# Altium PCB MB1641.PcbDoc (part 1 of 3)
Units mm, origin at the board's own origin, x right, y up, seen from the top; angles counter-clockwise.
Board outline 70 x 64.48 mm, 4 copper layers (Top Layer, GND, VCC, Bottom Layer), stack 1.502 mm thick; 161 components, 126 nets, 622 pads, 1092 vias.
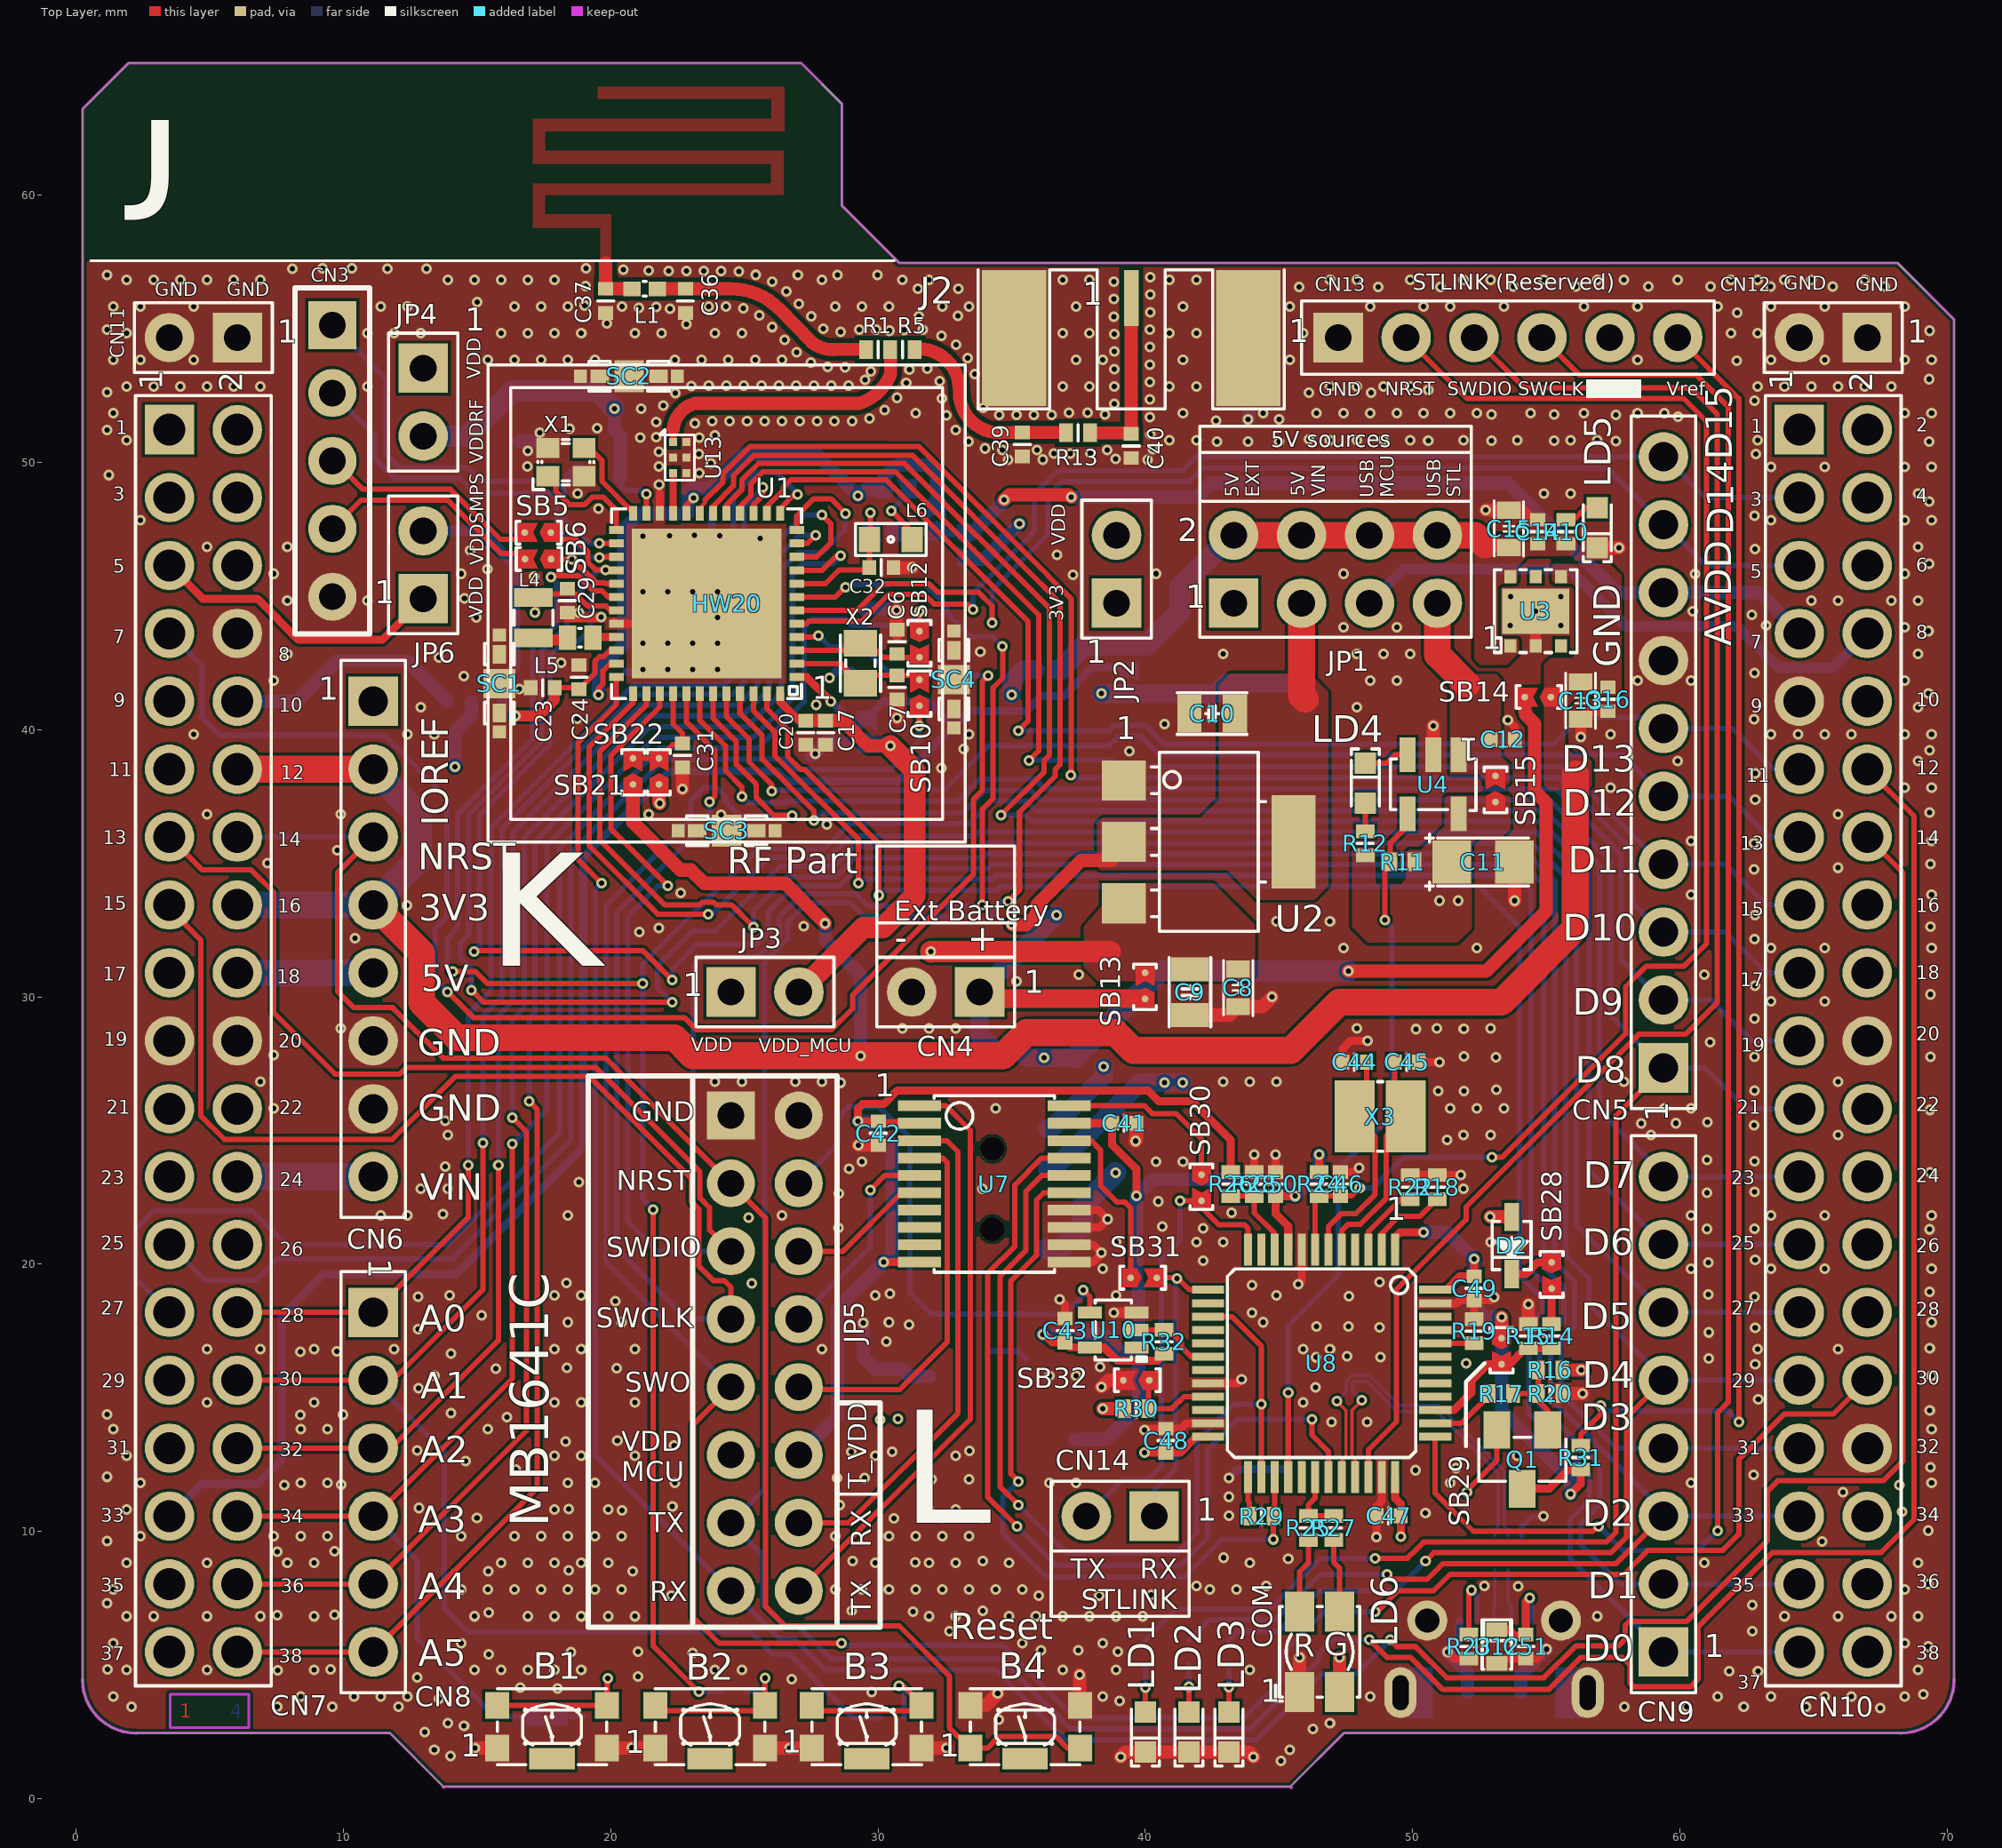
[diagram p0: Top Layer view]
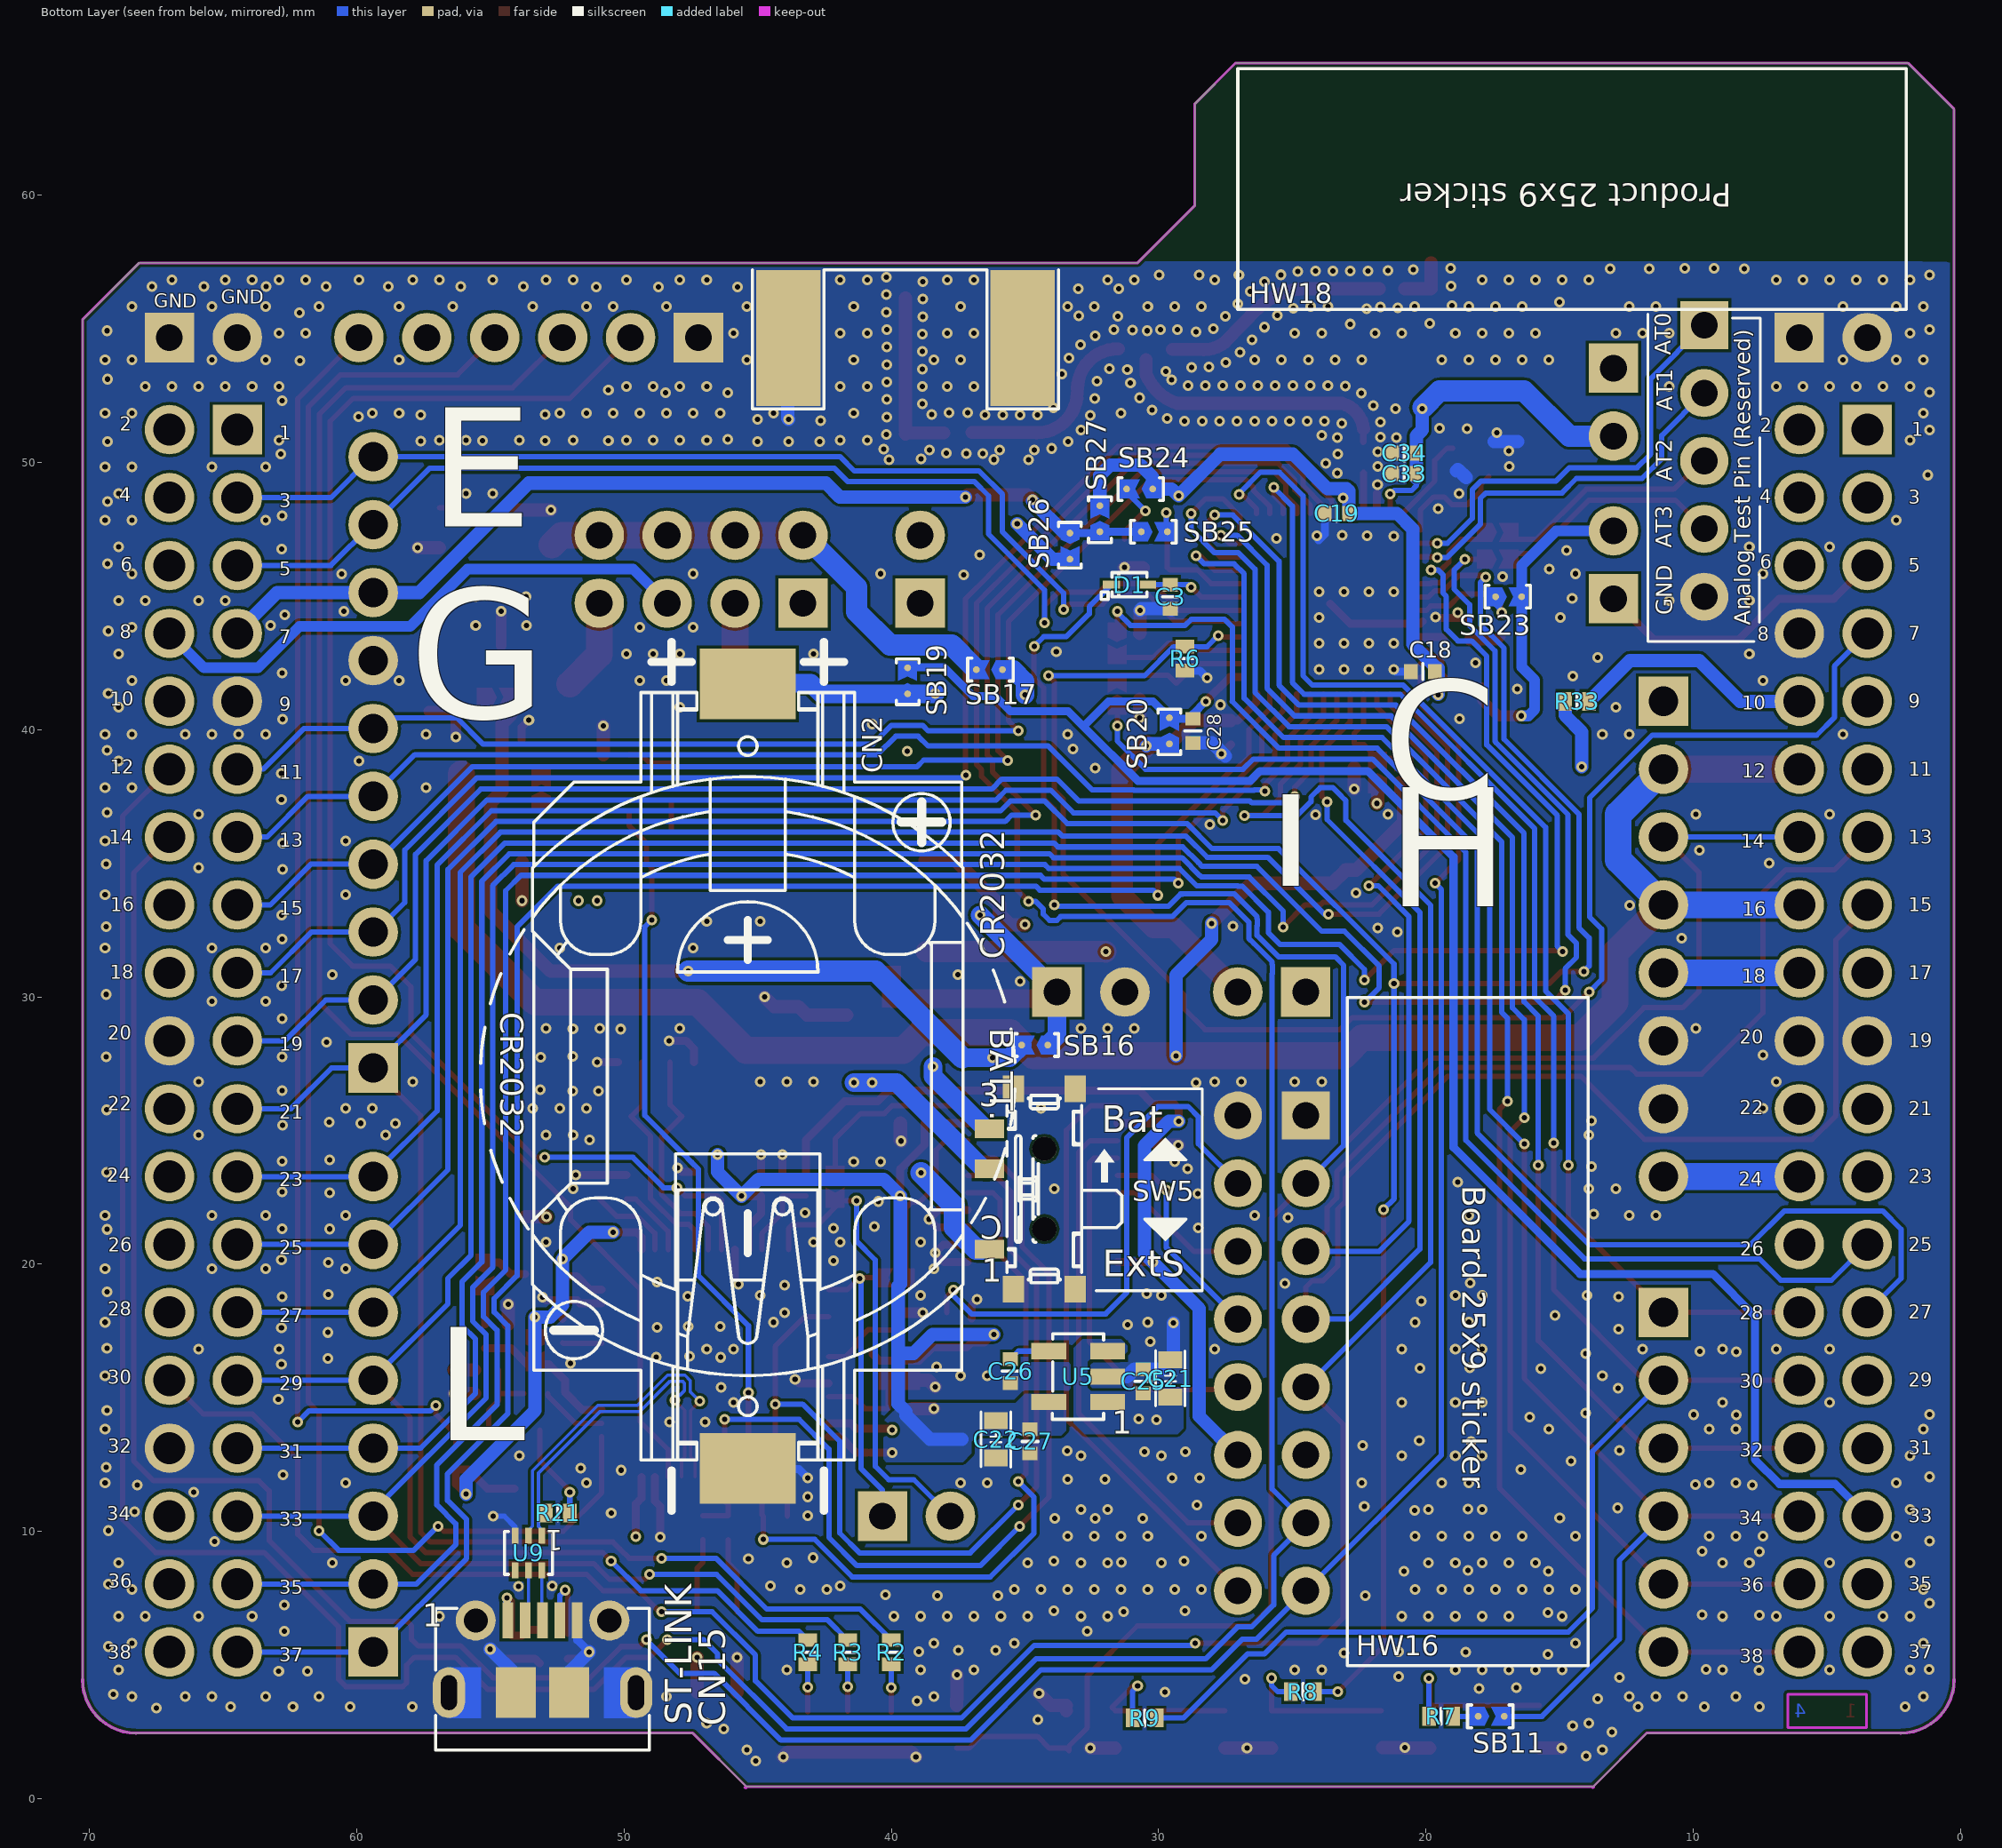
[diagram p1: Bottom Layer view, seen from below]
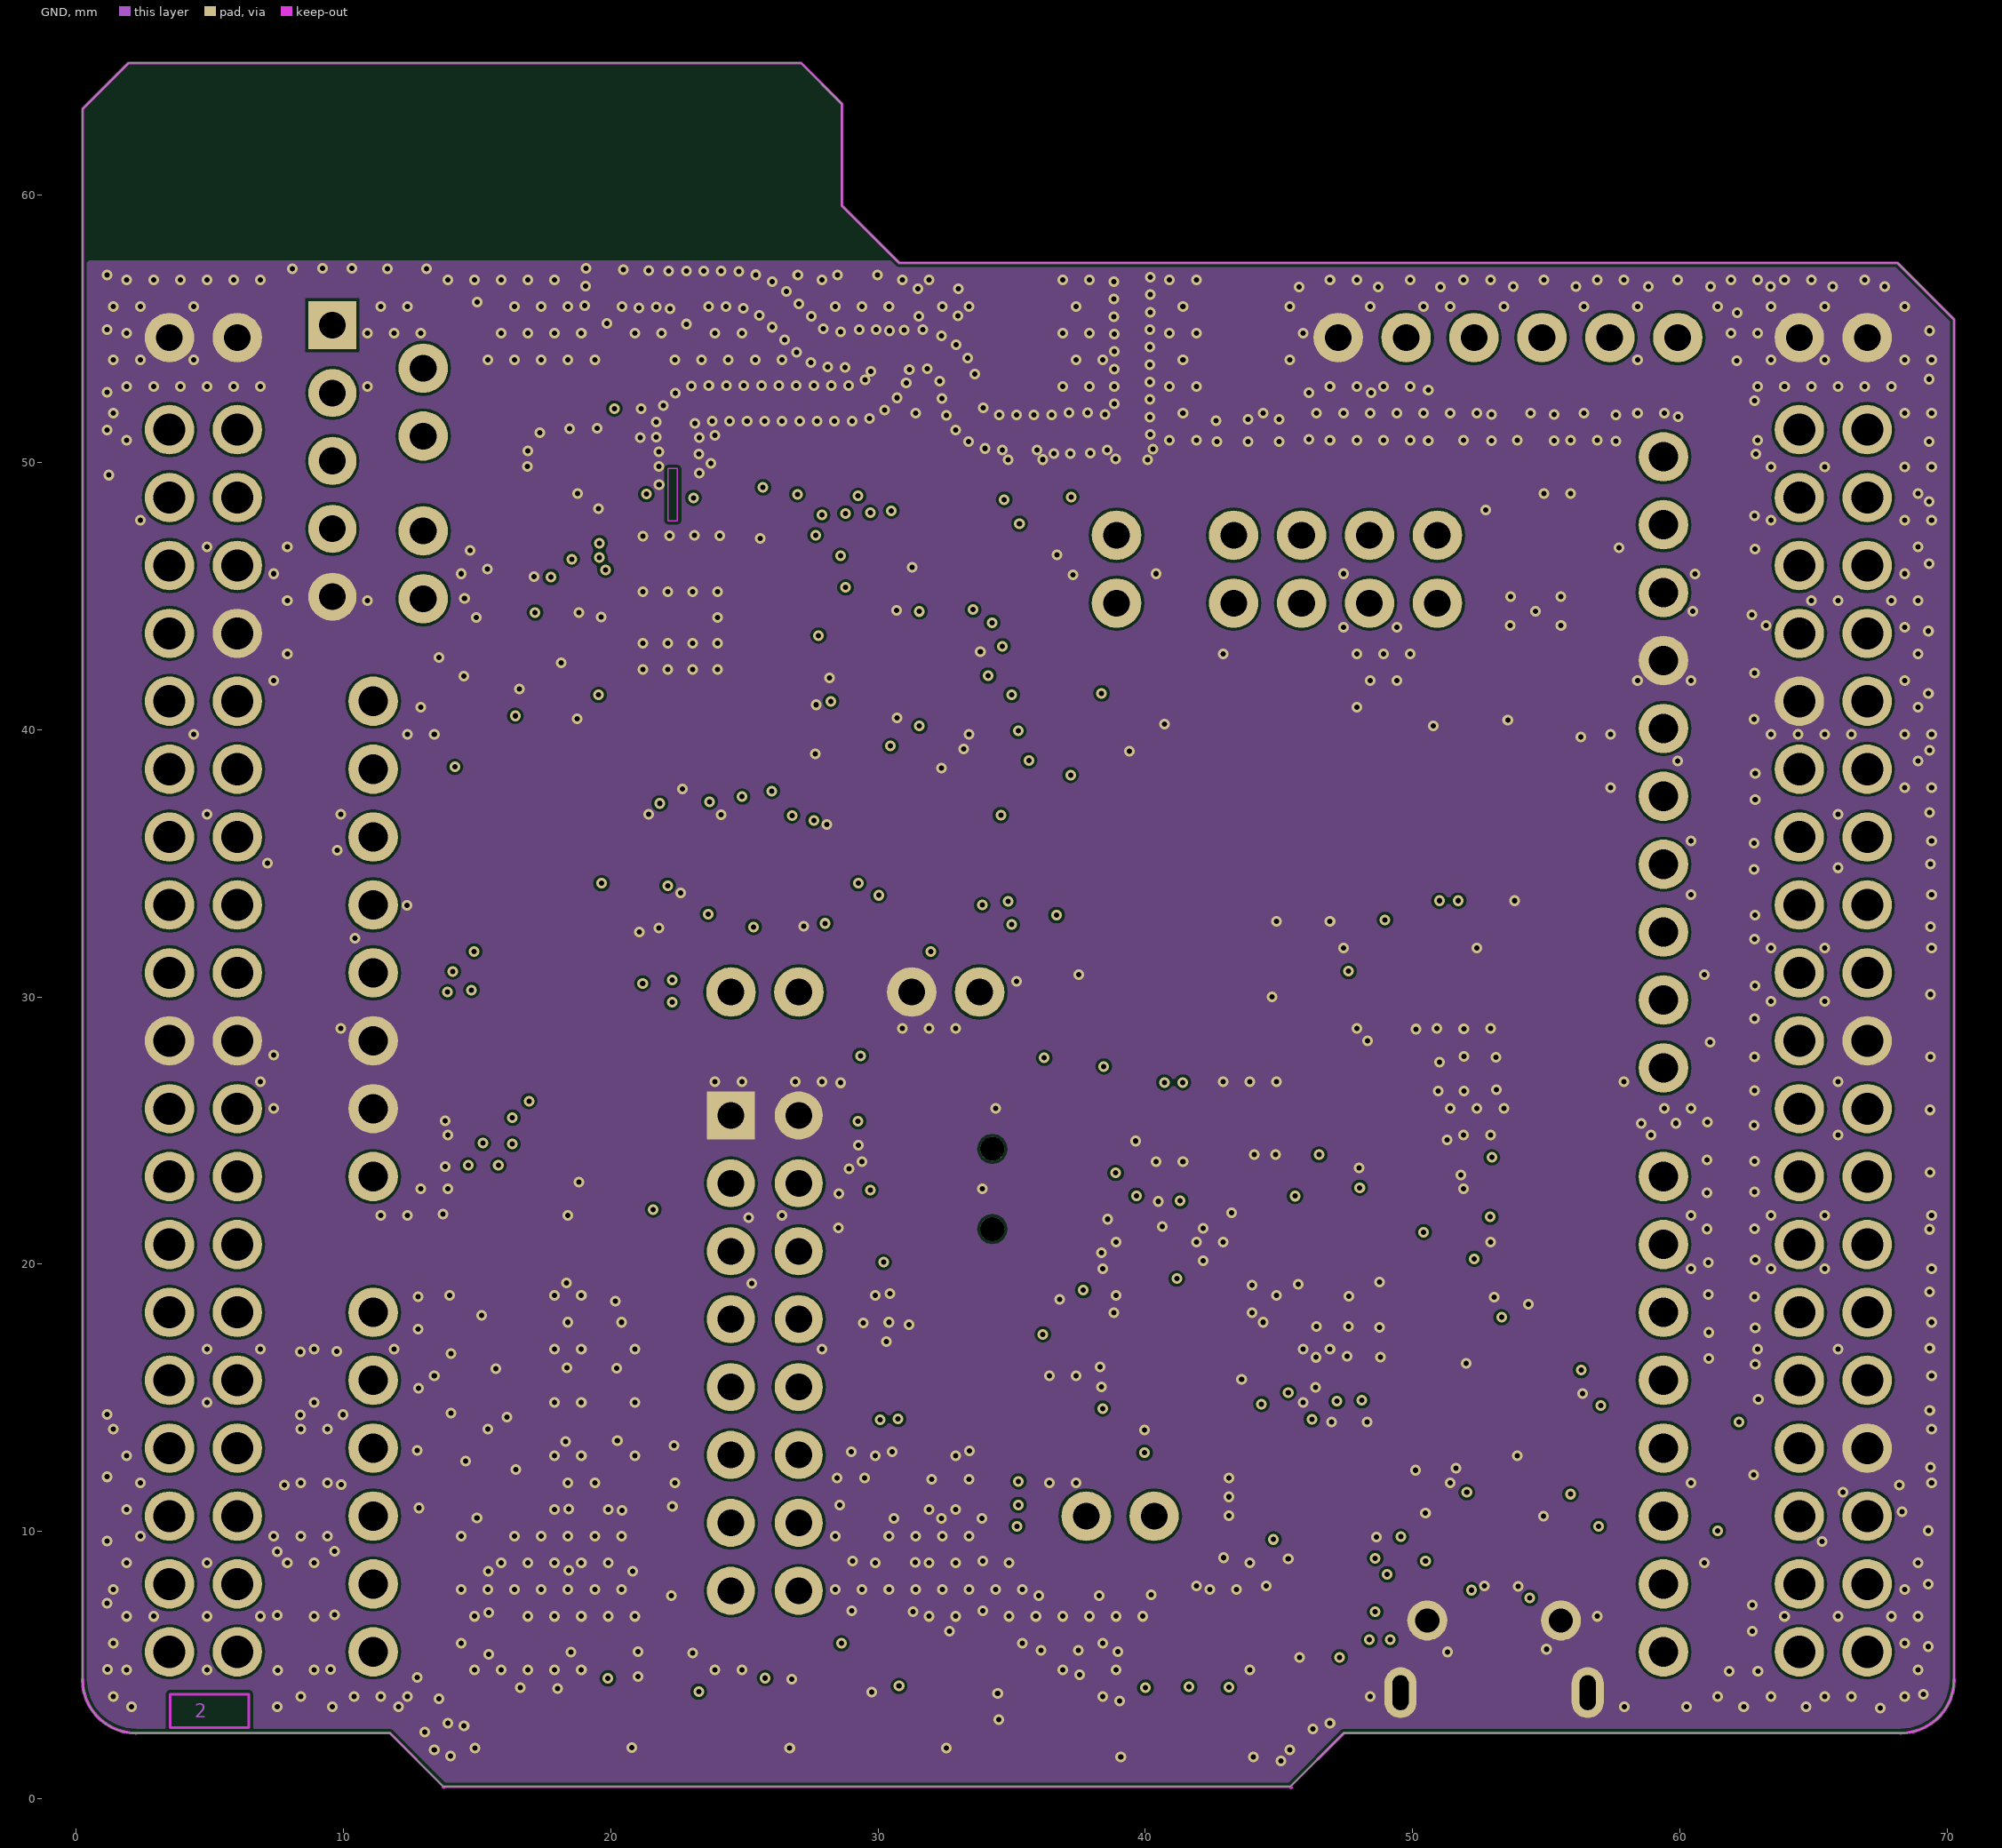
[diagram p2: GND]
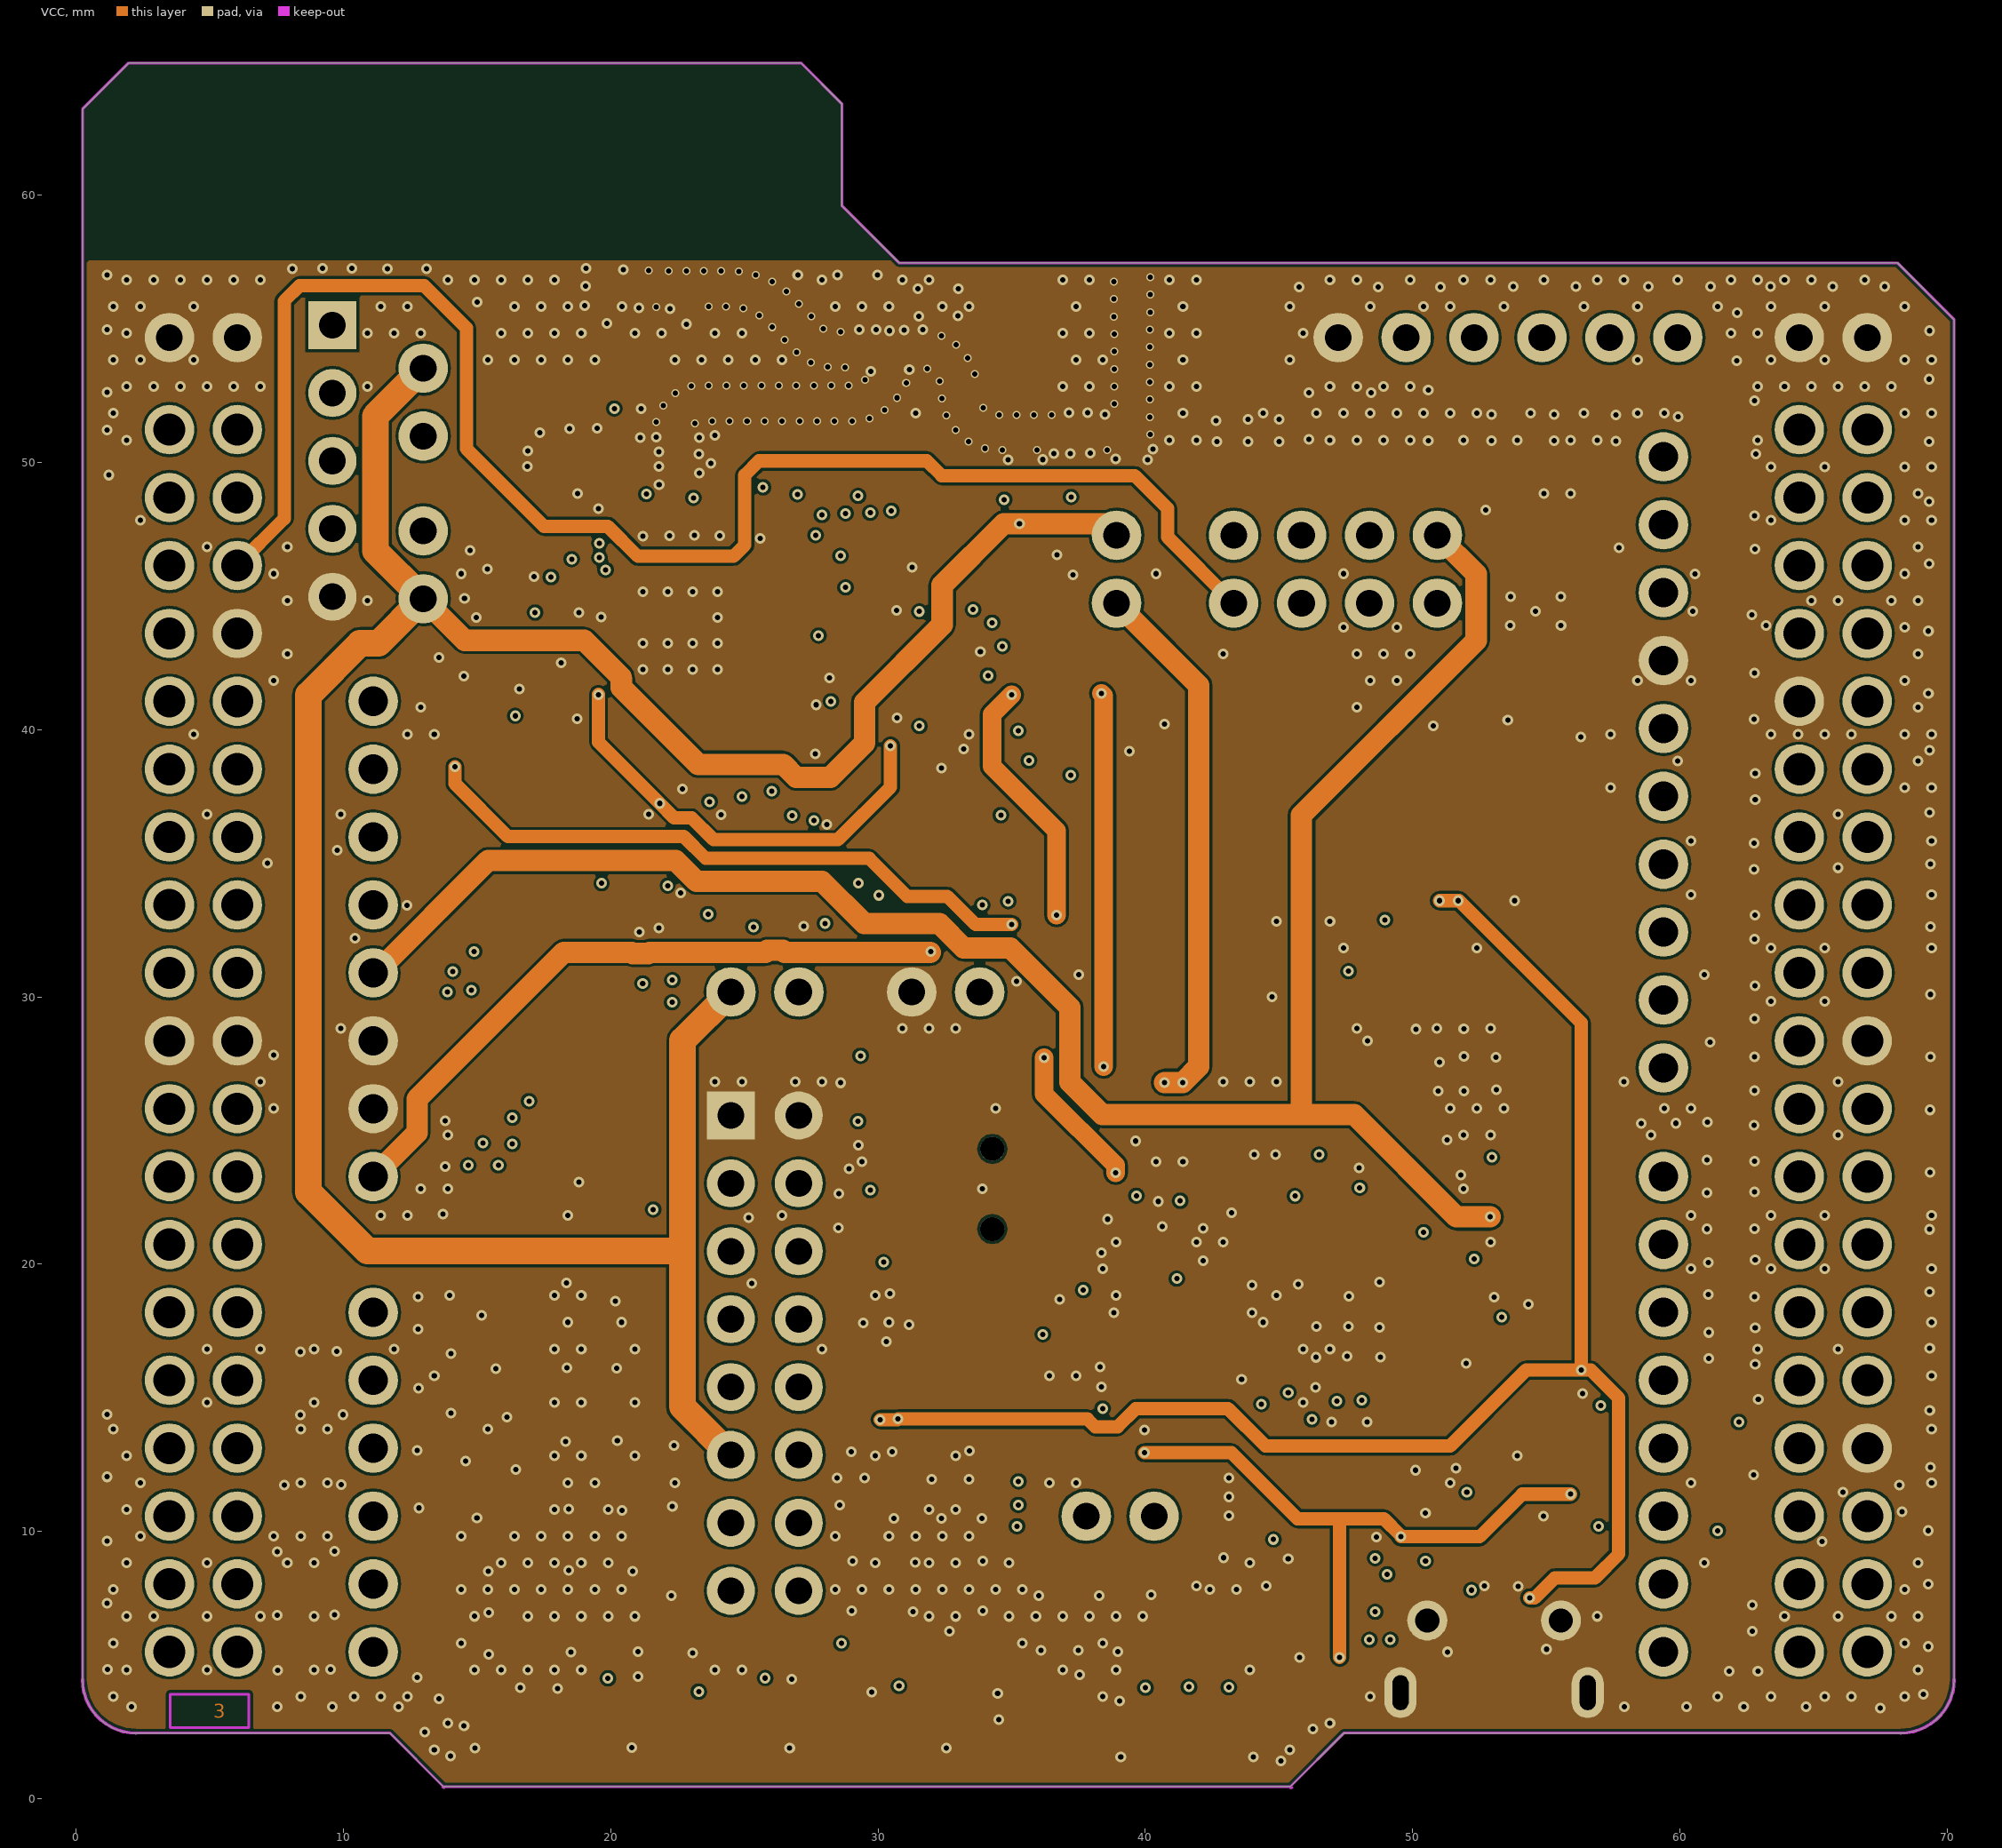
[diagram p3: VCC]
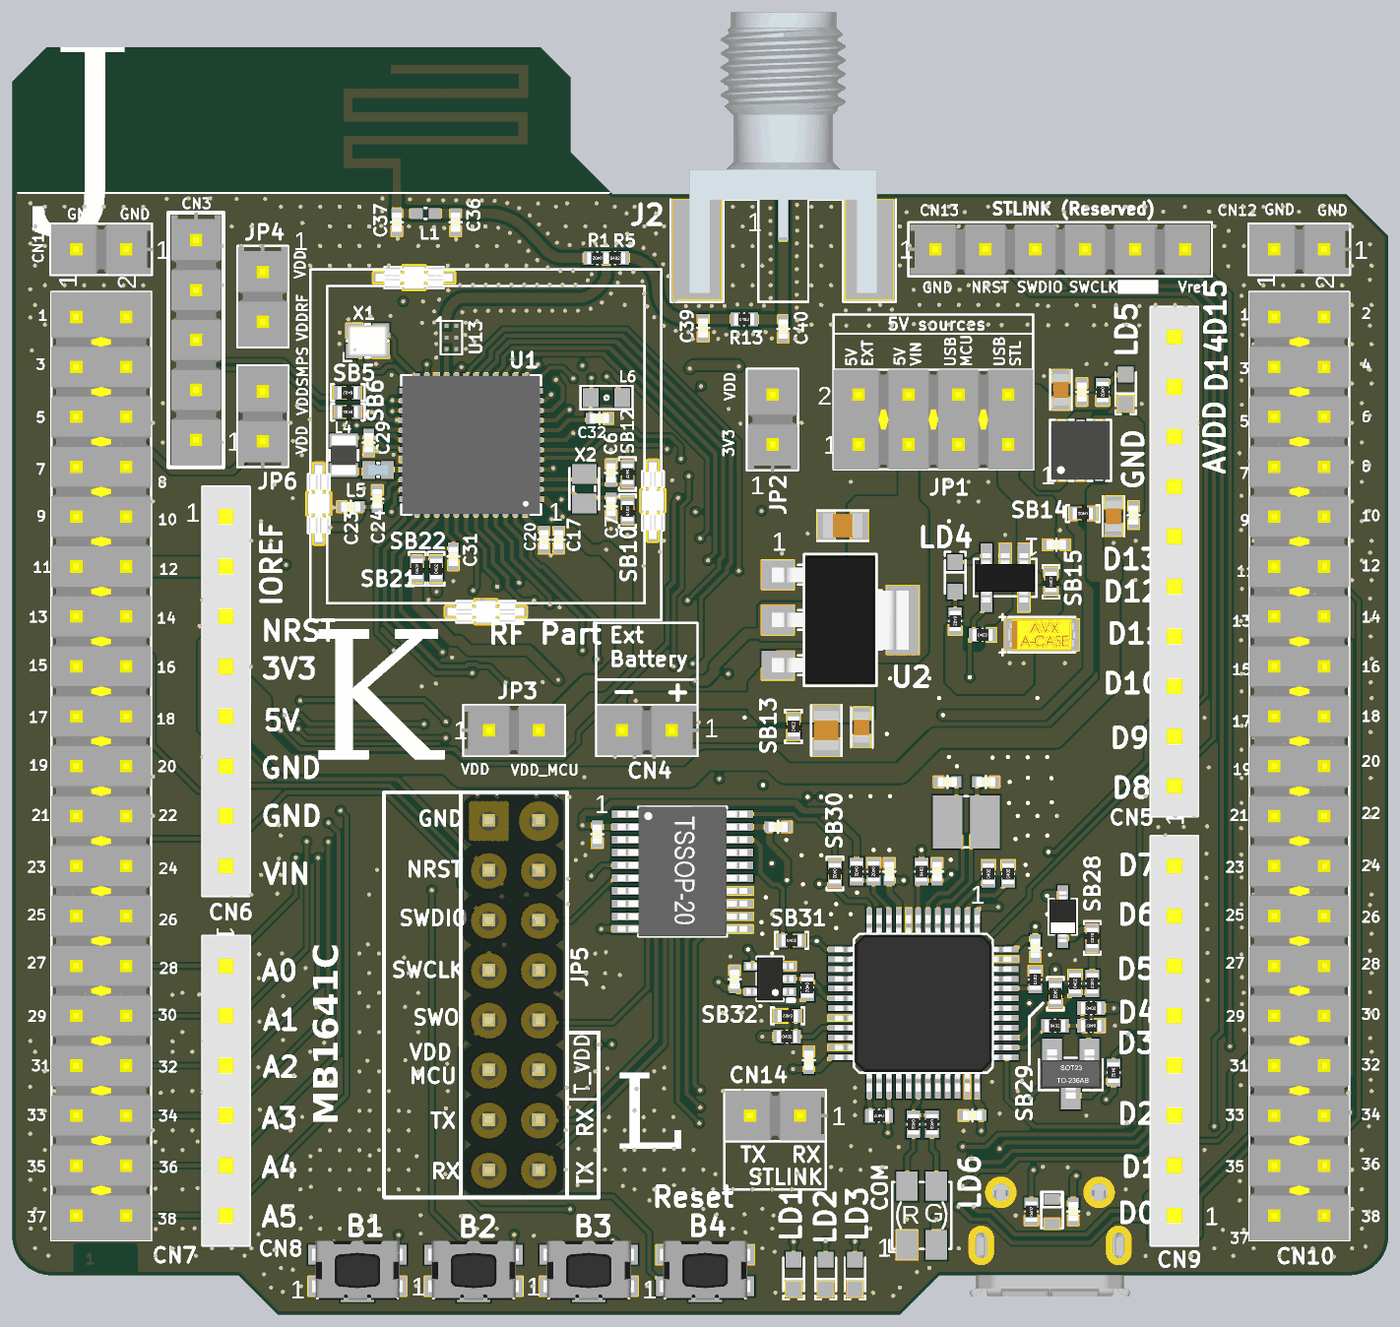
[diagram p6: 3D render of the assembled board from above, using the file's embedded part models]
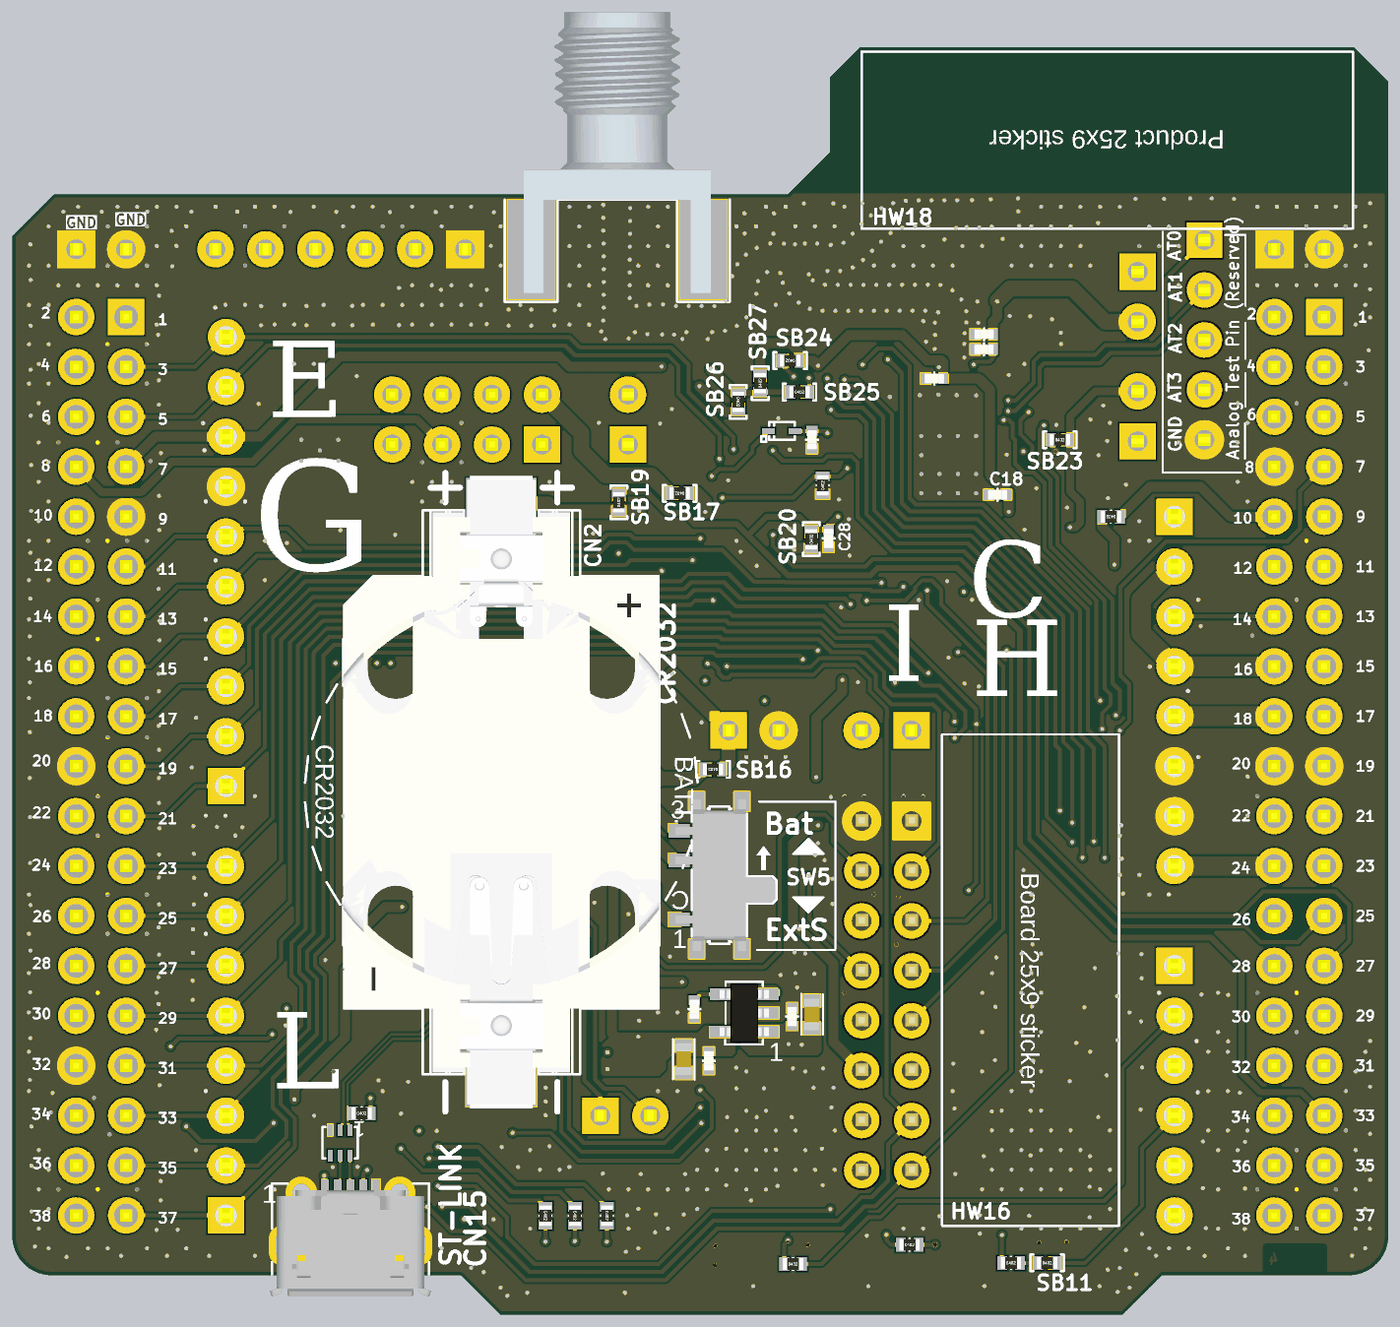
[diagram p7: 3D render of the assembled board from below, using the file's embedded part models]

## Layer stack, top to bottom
Top Solder: solder mask 0.015, Solder Resist, Dk 3.5
Top Layer: signal copper 0.012
Dielectric 1: core 0.5059, FR-4, Dk 4.2
GND: signal copper 0.018
Dielectric3: prepreg 0.43, FR-4, Dk 4.2
VCC: signal copper 0.018
Dielectric5: core 0.5062, FR-4, Dk 4.2
Bottom Layer: signal copper 0.012
Bottom Solder: solder mask 0.015, Solder Resist, Dk 3.5

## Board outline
2.25,2.46 11.75,2.46 13.751,0.459 45.423,0.459 47.424,2.46 68.25,2.46 ccw(c68.25,4.46) 70.25,4.46 70.25,55.336 68.126,57.46 30.788,57.46 28.646,59.602 28.646,63.412 27.122,64.936 1.976,64.936 0.25,63.21 0.25,57.46 0.25,4.46 ccw(c2.25,4.46)

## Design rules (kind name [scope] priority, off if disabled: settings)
Clearance "50ohms C39_2" [InNet('NetC39_2')] p1: gap=0.176 ignorepadtopadclearanceinfootprint=FALSE
Clearance "50ohms ANT" [InNet('ANT')] p2: gap=0.176 ignorepadtopadclearanceinfootprint=FALSE
Clearance "50ohms C36_2" [InNet('NetC36_2')] p3: gap=0.176 ignorepadtopadclearanceinfootprint=FALSE
Clearance "50ohms C40_2" [InNet('NetC40_2')] p4: gap=0.176 ignorepadtopadclearanceinfootprint=FALSE
Clearance A1 [Ispad and InNet('NetR1_1')] p5: gap=0.1 ignorepadtopadclearanceinfootprint=FALSE except(0.15: SMDPad-Poly)
Clearance "50 ohms R1_1" [InNet('NetR1_1')] p6: gap=0.176 ignorepadtopadclearanceinfootprint=FALSE
Clearance A3 [Ispad and InNet('NetU1_21')] p7: gap=0.1 ignorepadtopadclearanceinfootprint=FALSE except(0.15: SMDPad-Poly)
Clearance U1_21 [All vs InNet('NetU1_21')] p8: gap=0.176 ignorepadtopadclearanceinfootprint=FALSE
Clearance [All] p9: gap=0.102 ignorepadtopadclearanceinfootprint=FALSE
ComponentClearance [All] p1 off: gap=0.2 collisioncheckmode=3 verticalgap=0.2 showdistances=FALSE
DiffPairsRouting [All] p1: maxlimit=0.102 minlimit=0.102 mostfreqgap=0.102 toplayer_minwidth=0.12 toplayer_maxwidth=0.12 toplayer_prefwidth=0.12 midlayer1_minwidth=0.12 midlayer1_maxwidth=0.12 midlayer1_prefwidth=0.12 midlayer3_minwidth=0.12 midlayer3_maxwidth=0.12 midlayer3_prefwidth=0.12 bottomlayer_minwidth=0.12 bottomlayer_maxwidth=0.12 bottomlayer_prefwidth=0.12 maxuncoupledlength=12.7
Height [All] p1 off: minheight=0 maxheight=25.4 prefheight=12.7
HoleSize [All] p1: absolutevalues=TRUE maxlimit=12.7 minlimit=0.025 maxpercent=80.000 minpercent=20.000
HoleToHoleClearance [All] p1: gap=0.178 allowstackedmicrovias=TRUE
MinimumSolderMaskSliver [All] p1 off: minsoldermaskwidth=0.013
PasteMaskExpansion [All] p1 off: expansion=0
PlaneConnect [All] p1: planeconnectstyle=Relief reliefexpansion=0.508 reliefentries=4 reliefconductorwidth=0.254 reliefairgap=0.152
PolygonConnect PolygonConnect_via [IsVia] p1: connectstyle=Direct reliefconductorwidth=0.254 reliefentries=4 polygonreliefangle="90 Angle" airgapwidth=0.254
PolygonConnect [All] p2: connectstyle=Direct reliefconductorwidth=0.508 reliefentries=4 polygonreliefangle="90 Angle" airgapwidth=0.254
RoutingCorners [All] p1 off: cornerstyle=45-Degree minsetback=2.54 maxsetback=2.54
RoutingLayers [All] p1 off: top layer_v5=TRUE mid layer 1_v5=TRUE mid layer 3_v5=TRUE bottom layer_v5=TRUE
RoutingPriority [All] p1 off: routingpriority=0
RoutingTopology [All] p1 off: topology=Shortest
RoutingVias [All] p1: holewidth=0.254 width=0.508 viastyle="Through Hole" minholewidth=0.1 minwidth=0.25 maxholewidth=0.305 maxwidth=0.61
SilkToSilkClearance [All] p1 off: silktosilkclearance=0.013
SilkToSolderMaskClearance [IsPad] p1 off: minsilkscreentomaskgap=0.013 clearancetoexposedcopper=TRUE
SolderMaskExpansion [All] p1 off: expansion=0.102 istentingtop=FALSE
Width [All] p1: maxlimit=1.27 minlimit=0.089 preferedwidth=0.127 minimp=50.000000 maximp=50.000000 favimp=50.000000
16 further rules are at their usual default settings.

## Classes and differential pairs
component class U_HW_Mechanical_Parts: HW7 HW11 HW16 HW18
component class U_STM32_microcontroller_IOs: B1 B2 B3 B4 C3 C6 C7 CN3 D1 LD1 LD2 LD3 R2 R3 R4 R6 R7 R8 R9 SB5 SB6 SB10 SB11 SB12 X1 X2
component class U_Arduino_Mopho_Connectors: CN5 CN6 CN7 CN8 CN9 CN10 R33
component class U_Power: C8 C9 C10 C11 C12 C13 C14 C15 C16 C17 C18 C19 C20 C21 C22 C23 C24 C25 C26 C27 C28 C29 C31 C32 CN2 CN4 CN11 CN12 HW1 HW2 HW3 HW4 JP1 JP2 JP3 JP6 L4 L5 L6 LD4 LD5 R10 R11 R12 SB13 SB14 SB15 SB16 SB17 SB19 SB20 SB21 SB22 SB23 SB24 SB25 SB26 SB27 SW5 U2 U3 U4 U5
component class U_RF: C33 C34 C36 C37 C39 C40 HW7 HW20 J2 JP4 L1 R1 R5 R13 SC1 SC2 SC3 SC4 U1 U13
component class U_STLINK_V2-1: C41 C42 C43 C44 C45 C46 C47 C48 C49 C50 C51 CN13 CN14 CN15 D2 HW9 HW10 HW11 HW12 HW13 HW14 HW15 JP5 LD6 Q1 R14 R15 R16 R17 R18 R19 R20 R21 R22 R23 R24 R25 R26 R27 R28 R29 R30 R31 R32 SB28 SB29 SB30 SB31 SB32 U7 U8 U9 U10 U12 X3
net class DIFF90: USBSTLK_N USBSTLK_P
differential pair USBSTLK: +USBSTLK_P -USBSTLK_N

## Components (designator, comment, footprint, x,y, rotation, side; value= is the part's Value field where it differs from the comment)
B1 "SW-PUSH-CMS_KMR2_BLACK" SWI_C&K_Y78B23110FP__ITT_KMR231GLFS 17.81,2.7 r180 top value=KMR231GLFS
B2 "SW-PUSH-CMS_KMR2_BLACK" SWI_C&K_Y78B23110FP__ITT_KMR231GLFS 23.723,2.7 r180 top value=KMR231GLFS
B3 "SW-PUSH-CMS_KMR2_BLACK" SWI_C&K_Y78B23110FP__ITT_KMR231GLFS 29.579,2.7 r180 top value=KMR231GLFS
B4 "SW-PUSH-CMS_KMR2_BLACK" SWI_C&K_Y78B23110FP__ITT_KMR231GLFS 35.504,2.7 r180 top value=KMR231GLFS
C3 "Capacitor" C0402 29.562,44.971 r90 bottom value=100nF
C6 "Capacitor" C0402 30.712,41.578 r90 top value=10pF
C7 "Capacitor" C0402 30.712,43.283 r270 top value=10pF
C8 "Capacitor" C0603 43.47,30.339 r90 top value=100nF
C9 "Capacitor" C0805 41.67,30.177 r270 top value=10uF
C10 "Capacitor" C0805 42.5,40.6 r180 top value=10uF
C11 "Cap_POL_TANA" CPOL_TAJ-A_1206_H180 52.63,35.048 r0 top value=4.7uF
C12 "Capacitor" C0402 53.373,39.629 r180 top value=100nF
C13 "Capacitor" C0603 56.28,41.085 r90 top value=1uF
C14 "Capacitor" C0402 54.672,47.4 r270 top value=100nF
C15 "Capacitor" C0603 53.6,47.511 r270 top value=1uF
C16 "Capacitor" C0402 57.296,41.135 r90 top value=100nF
C17 "Capacitor" C0402 28.042,39.885 r90 top value=100nF
C18 "Capacitor" C0402 20.124,42.17 r180 bottom value=100nF
C19 "Capacitor" C0402 23.339,48.087 r180 bottom value=100nF
C20 "Capacitor" C0402 27.3,39.885 r90 top value=100nF
C21 "Capacitor" C0603 29.562,15.727 r270 bottom value=1uF
C22 "Capacitor" C0603 36.09,13.45 r90 bottom value=1uF
C23 "Capacitor" C0402 17.464,41.563 r0 top value=4.7uF
C24 "Capacitor" C0402 18.819,41.964 r270 top value=100nF
C25 "Capacitor" C0402 30.579,15.622 r270 bottom value=100nF
C26 "Capacitor" C0402 35.549,16 r90 bottom value=100nF
C27 "Capacitor" C0402 34.812,13.37 r90 bottom value=100nF
C28 "Capacitor" C0402 28.718,39.953 r270 bottom value=100nF
C29 "Capacitor" C0402 18.38,44.824 r90 top value=4.7uF
C31 "Capacitor" C0402 22.689,39.033 r90 top value=100nF
C32 "Capacitor" C0402 30.129,46.062 r180 top value=100nF
C33 "Capacitor" C0402 20.814,49.576 r180 bottom value=100nF
C34 "Capacitor" C0402 20.81,50.343 r180 bottom value=100pF
C36 "Capacitor" C0402 22.8,56.038 r90 top value=1.2pF
C37 "Capacitor" C0402 19.816,56.038 r90 top value=1.2pF
C39 "Capacitor" C0402 35.4,50.664 r90 top value=1.2pF
C40 "Capacitor" C0402 39.473,50.61 r90 top value=1.2pF
C41 "Capacitor" C0402 39.212,25.275 r0 top value=100nF
C42 "Capacitor" C0402 30.012,24.9 r90 top value=100nF
C43 "Capacitor" C0402 37,17.52 r90 top value=100nF
C44 "Capacitor" C0402 47.827,27.561 r180 top value=20pF
C45 "Capacitor" C0402 49.781,27.561 r0 top value=20pF
C46 "Capacitor" C0402 47.3,23 r270 top value=100nF
C47 "Capacitor" C0402 49.1,10.591 r0 top value=100nF
C48 "Capacitor" C0402 40.77,13.4 r270 top value=100nF
C49 "Capacitor" C0402 52.3,19.1 r90 top value=100nF
C50 "Capacitor" C0402 44.87,23 r270 top value=100nF
C51 "Capacitor" C0402 54.23,5.7 r270 top value=100pF
CN2 "BATTERY HOLDER" BAT_RENATA-SMTU2032-LF_KEYSTONE-1769533_CR2032_SMD_2P_DI 45.37,27.034 r270 bottom locked value="CR2032 holder"
CN3 "Header 5x1" CON_SAMTEC_TSW-105-07-X-S 9.596,50.051 r270 top
CN4 "Header 2x1" CON_SAMTEC_TSW-102-07-G-S 32.532,30.183 r180 top
CN5 "Socket 10x1" CON_SAMTEC_SSW-110-01-X-S 59.38,38.774 r90 top locked
CN6 "Socket 8x1" CON_SAMTEC_SSW-108-01-X-S 11.12,32.17 r270 top locked
CN7 "Header 19x2" CON_SAMTEC_TSW-119-09-X-D 4.77,28.36 r270 top locked
CN8 "Socket 6x1" CON_SAMTEC_SSW-106-01-X-S 11.12,11.85 r270 top locked
CN9 "Socket 8x1" CON_SAMTEC_SSW-108-01-X-S 59.38,14.39 r90 top locked
CN10 "Header 19x2" CON_SAMTEC_TSW-119-09-X-D 65.73,28.36 r270 top locked
CN11 "Jumper_Header 2x1 Fitted" CON_SAMTEC_TSW-102-07-G-S 4.77,54.664 r180 top locked value="Shunt Fitted"
CN12 "Jumper_Header 2x1 Fitted" CON_SAMTEC_TSW-102-07-G-S 65.73,54.664 r180 top locked value="Shunt Fitted"
CN13 "Header 6x1" CON_SAMTEC_TSW-106-07-X-S 53.564,54.664 r0 top locked
CN14 "Header 2x1" CON_SAMTEC_TSW-102-07-G-S 39.06,10.576 r180 top
CN15 "USB_uB_105017.0001" CON_USBMICROB_MOLEX_105017-0001_H2P90 53.045,2.525 r180 bottom locked value=USB_uB_105017-0001
D1 "SCHOTTKY_1A_2K" DIO_SOD523_1A_2K 31.094,45.421 r0 bottom value=BAT54KFILM
D2 "BAT60JFILM" DIO_SOD323 53.7,20.7 r270 top
HW16 "STICKER_BOARD" STICKER_BOARD_25X9 18.443,17.48 r270 bottom value="Sticker board"
HW18 "STICKER_PRODUCT" STICKER_PRODUCT_25X9 14.542,60.22 r0 bottom locked value="Sticker product"
HW20 "Daughter_Board" SHIELD_RF_ST-CUSTOM_17P2X17P2_H3 24.339,44.72 r90 top locked value="RF shield (17,2x17,2x3mm)"
J2 "SMA-J-P-H-ST-EM1" CON_SMA-RF_CINCH_142-0701-851 39.473,57.191 r0 top value=SMA_142-0701-851
JP1 "Jumper_Header 4x2" CON_SAMTEC_TSW-104-07-X-D 47.113,46 r0 top value=Jumper_Header_4x2
JP2 "Jumper_Header 2x1 Fitted" CON_SAMTEC_TSW-102-07-G-S 38.925,46 r90 top locked value="Shunt Fitted"
JP3 "Jumper_Header 2x1 Fitted" CON_SAMTEC_TSW-102-07-G-S 25.773,30.183 r0 top value="Shunt Fitted"
JP4 "Jumper_Header 2x1 Fitted" CON_SAMTEC_TSW-102-07-G-S 12.992,52.249 r270 top value="Shunt Fitted"
JP5 "Header 8x2" CON_SAMTEC_TSW-108-07-X-D 25.767,16.727 r270 top locked
JP6 "Jumper_Header 2x1 Fitted" CON_SAMTEC_TSW-102-07-G-S 12.992,46.164 r90 top value="Shunt Fitted"
L1 "Inductor" IND_0402_MURATA_LGQ15HS02_H0P5 21.275,56.488 r180 top value=3.6nH
L4 "Inductor" IND_0805_WURTH_74479777310A 17.114,44.184 r270 top value=74479777310A
L5 "Inductor" IND_0402_MURATA_LQW15AN_H0P5 18.863,43.437 r0 top value=10nH
L6 "BEAD" L0603 30.479,47.114 r180 top value=600R@100MHz
LD1 "LED_blue" LED_0603_VISHAY_VLMB1300-GS08_BLUE_1A2K_H0P8 40.004,2.5 r270 top value=BLUE
LD2 "LED_green" LED_0603_VISHAY_VLMTG1300-GS08_GREEN_1A2K_H0P8 41.631,2.5 r270 top value="TRUE GREEN"
LD3 "LED_red" LED_0603_VISHAY_VLMS1300-GS08_RED_1A2K_H0P8 43.124,2.5 r270 top value=RED
LD4 "LED_red" LED_0603_VISHAY_VLMS1300-GS08_RED_1A2K_H0P8 48.224,37.998 r90 top value=RED
LD5 "LED_green" LED_0603_VISHAY_VLMTG1300-GS08_GREEN_1A2K_H0P8 56.9,47.55 r270 top value="TRUE GREEN"
LD6 "LD_BICOLOR_CMS" LED_BI-GR_HSMF-A201-A00J1 46.52,5.5 r0 top
Q1 "9013-SOT23" NPN_SOT23 54.1,12.7 r180 top value="NPN SOT23"
R1 "Resistor" R0402 30.009,54.212 r180 top value=0R
R2 "Resistor" R0402 40,5.489 r270 bottom value=680R
R3 "Resistor" R0402 41.631,5.489 r270 bottom value=680R
R4 "Resistor" R0402 43.124,5.489 r270 bottom value=680R
R5 "Resistor" R0402 30.915,54.213 r0 top value=0R
R6 "Resistor" R0402 29.018,42.653 r90 bottom value=10K
R7 "Resistor" R0402 19.44,3.09 r180 bottom value=1K
R8 "Resistor" R0402 24.6,4.012 r180 bottom value=1K
R9 "Resistor" R0402 30.526,3.029 r180 bottom value=1K
R10 "Resistor" R0402 55.73,47.4 r270 top value=270R
R11 "Resistor" R0402 49.615,35.048 r0 top value=10K
R12 "Resistor" R0402 48.224,35.748 r270 top value=1K
R13 "Resistor" R0402 37.486,51.1 r0 top value=0R
R14 "Resistor" R0402 55.198,17.309 r270 top value=2K7
R15 "Resistor" R0402 54.326,17.309 r90 top value=4K7
R16 "Resistor" R0402 55.14,16.044 r0 top value=10K
R17 "Resistor" R0402 53.3,15.159 r0 top value=100R
R18 "Resistor" R0402 50.913,22.888 r90 top value=10K
R19 "Resistor" R0402 52.294,17.5 r90 top value=100K
R20 "Resistor" R0402 55.14,15.159 r180 top value=36K
R21 "Resistor" R0402 52.475,10.7 r180 bottom value=1K5
R22 "Resistor" R0402 49.913,22.888 r90 top value=10K
R23 "Resistor" R0402 52.1,5.7 r90 top value=100K
R24 "Resistor" R0402 46.5,23 r90 top value=100K
R25 "Resistor" R0402 46.095,10.138 r270 top value=100R
R26 "Resistor" R0402 43.2,23 r270 top value=4K7
R27 "Resistor" R0402 47.045,10.138 r270 top value=100R
R28 "Resistor" R0402 44.07,23 r270 top value=4K7
R29 "Resistor" R0402 44.345,10.576 r180 top value=100R
R30 "Resistor" R0402 39.662,14.6 r0 top value=10K
R31 "Resistor" R0402 56.28,12.769 r270 top value=10R
R32 "Resistor" R0402 40.7,17.1 r270 top value=100K
R33 "Resistor" R0402 14.35,41.06 r0 bottom value=1K
SB5 "SB_ON" SOLDER-BRIDGE_R0402-0R 17.314,47.369 r180 top
SB6 "SB_ON" SOLDER-BRIDGE_R0402-0R 17.323,46.38 r180 top
SB10 "SB_ON" SOLDER-BRIDGE_R0402-0R 31.552,41.341 r90 top
SB11 "SB_ON" SOLDER-BRIDGE_R0402-0R 17.6,3.09 r180 bottom
SB12 "SB_ON" SOLDER-BRIDGE_R0402-0R 31.552,43.229 r270 top
SB13 "SB_ON" SOLDER-BRIDGE_R0402-0R 39.99,30.38 r90 top
SB14 "SB_ON" SOLDER-BRIDGE_R0402-0R 54.716,41.216 r180 top
SB15 "SB_ON" SOLDER-BRIDGE_R0402-0R 53.096,37.742 r90 top
SB16 "SB_ON" SOLDER-BRIDGE_R0402-0R 34.6,28.2 r0 bottom locked
SB17 "SB_ON" SOLDER-BRIDGE_R0402-0R 36.295,42.243 r0 bottom
SB19 "SB_ON" SOLDER-BRIDGE_R0402-0R 39.39,41.787 r90 bottom
SB20 "SB_ON" SOLDER-BRIDGE_R0402-0R 29.6,39.916 r90 bottom
SB21 "SB_ON" SOLDER-BRIDGE_R0402-0R 20.839,38.4 r90 top
SB22 "SB_ON" SOLDER-BRIDGE_R0402-0R 21.81,38.4 r90 top
SB23 "SB_ON" SOLDER-BRIDGE_R0402-0R 16.95,44.971 r180 bottom
SB24 "SB_ON" SOLDER-BRIDGE_R0402-0R 30.675,49 r0 bottom
SB25 "SB_ON" SOLDER-BRIDGE_R0402-0R 30.2,47.4 r180 bottom
SB26 "SB_ON" SOLDER-BRIDGE_R0402-0R 33.32,46.9 r270 bottom
SB27 "SB_ON" SOLDER-BRIDGE_R0402-0R 32.2,47.85 r90 bottom
SB28 "SB_ON" SOLDER-BRIDGE_R0402-0R 55.198,19.619 r270 top
SB29 "SB_ON" SOLDER-BRIDGE_R0402-0R 53.323,16.784 r270 top
SB30 "SB_ON" SOLDER-BRIDGE_R0402-0R 42.1,22.9 r270 top
SB31 "SB_ON" SOLDER-BRIDGE_R0402-0R 39.9,19.494 r0 top
SB32 "SB_ON" SOLDER-BRIDGE_R0402-0R 39.7,15.66 r180 top
SC1 "Shield-clip_S0951-46R" CLIP_HARWIN_S0951-46R 15.839,41.72 r90 top value=S0951-46R
SC2 "Shield-clip_S0951-46R" CLIP_HARWIN_S0951-46R 20.69,53.22 r180 top value=S0951-46R
SC3 "Shield-clip_S0951-46R" CLIP_HARWIN_S0951-46R 24.34,36.22 r180 top value=S0951-46R
SC4 "Shield-clip_S0951-46R" CLIP_HARWIN_S0951-46R 32.84,41.87 r90 top value=S0951-46R
SW5 "SW_MECA" SWI_SPDT-RA_TE-CONNECTIVITY_MLL1200S_1P2T 34.277,22.815 r90 bottom locked value=MLL1200S
U1 "STM32WB15_QFN48" ICC_UFQFPN48-EPAD_7X7_H0P55_P050 23.589,44.712 r180 top value=STM32WB15CCU6
U2 "LD1117S50TR" REG_SOT223-TAB 42.375,35.8 r270 top
U3 "LD39050PU33R" ICC_DFN6-EPAD_3X3_P095 54.6,44.43 r0 top
U4 "TPS2041C" MOS_SOT23-5L 50.764,37.954 r180 top
U5 "LD3985M33R" REG_SOT23-5L 33.01,15.8 r90 bottom locked
U7 "TXS0108EPWR" ICC_TSSOP20_6P50X4P40_P065 34.352,23 r270 top
U8 "STM32F103CBT6" ICC_LQFP48_7X7_P050 46.595,16.294 r180 top locked
U9 "ECMF02-2AMX6" ESD_QFN-6L_1P7X1P5_P050 53.574,9.2 r0 bottom locked
U10 "74LVC1G07GW-Q100" ICC_TSSOP5_SOT353-1_2P05X1P25_P065 38.8,17.54 r90 top value="Buffer/Driver 1-CH"
U12 "ESD-TRANSIL" ESD_QFN2_1P6X1_P125 53.15,5.7 r270 top value=ESDA7P60-1U1M
U13 "MLPF-WB55-01E3" ICC_BUMPLESS-CSP6_AN2348-FLIP-CHIP_1X1P60_P050-P0587 22.589,50.174 r0 top
X1 "XTAL_4_PINS" CRY_NX2016SA_4P 18.327,50.004 r0 top value="NX2016SA 32MHz"
X2 "XTAL_2_PINS" CRY_NX2012SA_2P 29.347,42.479 r90 top value="NX2012SA 32.768kHz"
X3 "XTAL_2_PINS" CRY_NX3225GD_2P 48.785,25.529 r0 top value="NX3225GD 8MHz"

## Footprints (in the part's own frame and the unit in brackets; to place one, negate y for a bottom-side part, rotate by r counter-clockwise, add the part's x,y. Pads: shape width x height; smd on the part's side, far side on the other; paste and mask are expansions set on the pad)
BAT_RENATA-SMTU2032-LF_KEYSTONE-1769533_CR2032_SMD_2P_DI [mm] "MCD-02071_DI"
  rect 2.65x3.6 smd mask+0.05: 1(-14.675,0) 2(14.675,0)
  silkscreen extent -16.25,-9.99 16.25,9.99, body extent -16.1,-10 16.1,10.02, height 5.6
C0402 [mm]
  rect 0.51x0.56 smd mask+0.05: 1(-0.45,0) 2(0.45,0)
  silkscreen extent 0,-0.3 0,0.3, body extent -0.5,-0.3 0.5,0.3, height 0.4
C0603 [mm]
  rect 0.64x0.89 smd mask+0.05: 1(-0.7,0) 2(0.7,0)
  silkscreen extent -1.05,-0.55 1.02,0.55, body extent -0.9,-0.5 0.9,0.5, height 1.4
C0805 [mm]
  rect 0.9x1.4 smd mask+0.05: 1(-0.85,0) 2(0.85,0)
  silkscreen extent -1.3,-0.77 1.3,0.77, body extent -1.1,-0.7 1.1,0.7, height 1.35
CLIP_HARWIN_S0951-46R [mm] "MCD-01587_CLIP-X1"
  rect 0.48x0.5 smd mask+0.1: 1(-1.81,0) 1(1.81,0)
  rect 0.7x0.5 smd mask+0.1: 1(-1.1,0) 1(1.1,0)
  rect 1.1x1.2 smd mask+0.1: 1(0,0)
  silkscreen extent -1.5,-0.55 1.5,0.55, body extent -2.05,-0.65 2.05,0.65, height 1.28
CON_SAMTEC_SSW-106-01-X-S [mm] "MCD-02079"
  rect 1.85x1.85 / inner round 1.85 / far side rect 1.85x1.85 hole 1.1 mask+0.05: 1(-6.35,0)
  round 1.85 hole 1.1 mask+0.05: 2(-3.81,0) 3(-1.27,0) 4(1.27,0) 5(3.81,0) 6(6.35,0)
  silkscreen extent -7.88,-1.2 7.88,1.2, body extent -7.88,-1.21 7.88,1.21, height 8.51
CON_SAMTEC_SSW-108-01-X-S [mm] "MCD-01743"
  rect 1.85x1.85 / inner round 1.85 / far side rect 1.85x1.85 hole 1.1 mask+0.05: 1(-8.89,0)
  round 1.85 hole 1.1 mask+0.05: 2(-6.35,0) 3(-3.81,0) 4(-1.27,0) 5(1.27,0) 6(3.81,0) 7(6.35,0) 8(8.89,0)
  silkscreen extent -10.42,-1.2 10.42,1.2, body extent -10.42,-1.21 10.42,1.21, height 8.51
CON_SAMTEC_SSW-110-01-X-S [mm] "MCD-02080"
  rect 1.85x1.85 / inner round 1.85 / far side rect 1.85x1.85 hole 1.1 mask+0.05: 1(-11.43,0)
  round 1.85 hole 1.1 mask+0.05: 2(-8.89,0) 3(-6.35,0) 4(-3.81,0) 5(-1.27,0) 6(1.27,0) 7(3.81,0) 8(6.35,0) 9(8.89,0) 10(11.43,0)
  silkscreen extent -12.96,-1.2 12.96,1.2, body extent -12.96,-1.21 12.96,1.21, height 8.51
CON_SAMTEC_TSW-102-07-G-S [mm]
  rect 1.85x1.85 / inner round 1.85 / far side rect 1.85x1.85 hole 1 mask+0.05: 1(-1.27,0)
  round 1.85 hole 1 mask+0.05: 2(1.27,0)
  silkscreen extent -2.58,-1.3 2.58,1.3, body extent -2.67,-1.3 2.58,1.3, height 8.38
CON_SAMTEC_TSW-104-07-X-D [mm]
  rect 1.85x1.85 / inner round 1.85 / far side rect 1.85x1.85 hole 1 mask+0.05: 1(-3.81,-1.27)
  round 1.85 hole 1 mask+0.05: 2(-3.81,1.27) 3(-1.27,-1.27) 4(-1.27,1.27) 5(1.27,-1.27) 6(1.27,1.27) 7(3.81,-1.27) 8(3.81,1.27)
  silkscreen extent -5.08,-2.54 5.08,2.54, body extent -5.08,-2.54 5.08,2.54, height 8.38
CON_SAMTEC_TSW-105-07-X-S [mm] "MCD-02060"
  rect 1.8x1.8 hole 1: 1(-5.08,0)
  round 1.8 hole 1: 2(-2.54,0) 3(0,0) 4(2.54,0) 5(5.08,0)
  silkscreen extent -6.48,-1.4 6.48,1.4, body extent -6.48,-1.27 6.35,1.27, height 8.38
CON_SAMTEC_TSW-106-07-X-S [mm]
  rect 1.85x1.85 / inner round 1.85 / far side rect 1.85x1.85 hole 1 mask+0.05: 1(-6.35,0)
  round 1.85 hole 1 mask+0.05: 2(-3.81,0) 3(-1.27,0) 4(1.27,0) 5(3.81,0) 6(6.35,0)
  silkscreen extent -7.73,-1.37 7.72,1.37, body extent -7.75,-1.37 7.72,1.37, height 8.38
CON_SAMTEC_TSW-108-07-X-D [mm] "MCD-02061"
  rect 1.8x1.8 hole 1: 1(-8.84,-1.27)
  round 1.8 hole 1: 2(-8.84,1.27) 3(-6.3,-1.27) 4(-6.3,1.27) 5(-3.76,-1.27) 6(-3.76,1.27) 7(-1.22,-1.27) 8(-1.22,1.27) 9(1.32,-1.27) 10(1.32,1.27) 11(3.86,-1.27) 12(3.86,1.27) 13(6.4,-1.27) 14(6.4,1.27) 15(8.94,-1.27) 16(8.94,1.27)
  silkscreen extent -10.31,-2.7 10.31,2.7, body extent -10.15,-2.55 10.17,2.53, height 8.5
CON_SAMTEC_TSW-119-09-X-D [mm]
  rect 1.85x1.85 / inner round 1.85 / far side rect 1.85x1.85 hole 1.2 mask+0.05: 1(-22.86,-1.27)
  round 1.85 hole 1.2 mask+0.05: 2(-22.86,1.27) 3(-20.32,-1.27) 4(-20.32,1.27) 5(-17.78,-1.27) 6(-17.78,1.27) 7(-15.24,-1.27) 8(-15.24,1.27) 9(-12.7,-1.27) 10(-12.7,1.27) 11(-10.16,-1.27) 12(-10.16,1.27) 13(-7.62,-1.27) 14(-7.62,1.27) 15(-5.08,-1.27) 16(-5.08,1.27) 17(-2.54,-1.27) 18(-2.54,1.27) 19(0,-1.27) 20(0,1.27) 21(2.54,-1.27) 22(2.54,1.27) 23(5.08,-1.27) 24(5.08,1.27) 25(7.62,-1.27) 26(7.62,1.27) 27(10.16,-1.27) 28(10.16,1.27) 29(12.7,-1.27) 30(12.7,1.27) 31(15.24,-1.27) 32(15.24,1.27) 33(17.78,-1.27) 34(17.78,1.27) 35(20.32,-1.27) 36(20.32,1.27) 37(22.86,-1.27) 38(22.86,1.27)
  silkscreen extent -24.13,-2.54 24.13,2.54, body extent -24.13,-2.55 24.13,2.54, height 8.38
CON_SMA-RF_CINCH_142-0701-851 [mil] "MCD-02072"
  rect 21.65x82.68 smd mask+1.97: 1(0,-41.37)
  rect 95x200 smd mask+1.97: 2(172.48,-100) 3(-172.48,-100)
  rect 95x200 smd far side mask+1.97: 4(-172.48,-100) 5(172.48,-100)
  silkscreen extent -225,-205 225,0, body extent -189,-187 189,376, height 161
CON_USBMICROB_MOLEX_105017-0001_H2P90 [mm]
  rect 0.4x1.35 smd mask+0.05: 1(-1.3,4.15) 2(-0.65,4.15) 3(0,4.15) 4(0.65,4.15) 5(1.3,4.15)
  round 1.5 hole 0.9 mask+0.05: 6(-2.5,4.15) 7(2.5,4.15)
  oval 1.2x1.9 hole 0.6 slot 1.3 at 90 deg mask+0.05: 8(3.5,1.45) 9(-3.5,1.45)
  rect 1.5x1.9 smd mask+0.05: 10(-1,1.45) 11(1,1.45)
  Top Layer region: 2.3,2.4 3.5,2.4 3.5,0.5 2.3,0.5 2.3,2.4
  Top Layer region: -3.5,2.4 -2.3,2.4 -2.3,0.5 -3.5,0.5 -3.5,2.4
  silkscreen extent -4,-0.7 4,4.6, body extent -4.1,-1.15 4.1,4.66, height 2.9
CPOL_TAJ-A_1206_H180 [mm]
  rect 1.45x1.6 smd mask+0.05: 1(-1.175,0) 2(1.175,0)
  silkscreen extent -2.15,-1.05 1.7,1.05, body extent -1.7,-0.9 1.7,0.9, height 1.8
CRY_NX2012SA_2P [mm]
  rect 1x1.25 smd mask+0.05: 1(-0.75,0) 2(0.75,0)
  silkscreen extent -1.05,-0.75 1.05,0.75, body extent -1.05,-0.63 1.05,0.63, height 0.6
CRY_NX2016SA_4P [mm]
  rect 0.85x0.75 smd mask+0.05: 1(-0.675,-0.525) 2(0.675,-0.525) 3(0.675,0.525) 4(-0.675,0.525)
  silkscreen extent -1.22,-1.02 1.05,0.85, body extent -1.05,-0.85 1.05,0.85, height 0.7
CRY_NX3225GD_2P [mm]
  rect 1.5x2.7 smd mask+0.05: 1(-0.95,0) 2(0.95,0)
  silkscreen extent -0.1,-1.3 0.1,1.3, body extent -1.65,-1.3 1.65,1.3, height 1
DIO_SOD323 [mm]
  rect 1.06x0.54 smd mask+0.05: 1(-1.07,0) 2(1.07,0)
  silkscreen extent -0.9,-0.72 0.9,0.72, body extent -1.3,-0.78 1.3,0.78, height 1.17
DIO_SOD523_1A_2K [mm] "MCD-01677"
  rect 0.65x0.3 smd mask+0.05: 1(-0.675,0) 2(0.675,0)
  silkscreen extent -0.65,-0.45 1.05,0.55, body extent -0.85,-0.45 0.85,0.45, height 0.71
ESD_QFN2_1P6X1_P125 [mm]
  rect 0.55x0.8 smd mask+0.05: 1(-0.625,0) 2(0.625,0)
  silkscreen extent -1,-0.55 0.85,0.55, body extent -0.85,-0.55 0.85,0.55, height 0.61
ESD_QFN-6L_1P7X1P5_P050 [mm]
  rect 0.25x0.6 smd mask+0.05: 1(-0.5,-0.65) 2(0,-0.65) 3(0.5,-0.65) 4(0.5,0.65) 5(0,0.65) 6(-0.5,0.65)
  silkscreen extent -0.9,-0.8 0.9,0.8, body extent -0.9,-0.8 0.9,0.8, height 0.56
ICC_BUMPLESS-CSP6_AN2348-FLIP-CHIP_1X1P60_P050-P0587 [mm] "MCD-02059"
  rect 0.3x0.3 smd paste-0.05 mask-0.05: A1(-0.25,0.587) A2(-0.25,0) A3(-0.25,-0.587) B1(0.25,0.587) B2(0.25,0) B3(0.25,-0.587)
  silkscreen extent -0.75,-0.85 0.55,1.04, body extent -0.51,-0.81 0.51,0.81, height 0.46
ICC_DFN6-EPAD_3X3_P095 [mm]
  rect 0.45x0.5 smd mask+0.05: 1(-0.95,-1.3) 2(0,-1.3) 3(0.95,-1.3) 4(0.95,1.3) 5(0,1.3) 6(-0.95,1.3)
  rect 2.5x1.7 smd mask+0.05: EP(0,0)
  silkscreen extent -1.55,-1.55 1.55,1.55, body extent -1.55,-1.55 1.55,1.55, height 1
ICC_LQFP48_7X7_P050 [mm]
  rect 0.3x1.2 smd mask+0.05: 1(-2.75,-4.25) 2(-2.25,-4.25) 3(-1.75,-4.25) 4(-1.25,-4.25) 5(-0.75,-4.25) 6(-0.25,-4.25) 7(0.25,-4.25) 8(0.75,-4.25) 9(1.25,-4.25) 10(1.75,-4.25) 11(2.25,-4.25) 12(2.75,-4.25) 25(2.75,4.25) 26(2.25,4.25) 27(1.75,4.25) 28(1.25,4.25) 29(0.75,4.25) 30(0.25,4.25) 31(-0.25,4.25) 32(-0.75,4.25) 33(-1.25,4.25) 34(-1.75,4.25) 35(-2.25,4.25) 36(-2.75,4.25)
  rect 1.2x0.3 smd mask+0.05: 13(4.25,-2.75) 14(4.25,-2.25) 15(4.25,-1.75) 16(4.25,-1.25) 17(4.25,-0.75) 18(4.25,-0.25) 19(4.25,0.25) 20(4.25,0.75) 21(4.25,1.25) 22(4.25,1.75) 23(4.25,2.25) 24(4.25,2.75) 37(-4.25,2.75) 38(-4.25,2.25) 39(-4.25,1.75) 40(-4.25,1.25) 41(-4.25,0.75) 42(-4.25,0.25) 43(-4.25,-0.25) 44(-4.25,-0.75) 45(-4.25,-1.25) 46(-4.25,-1.75) 47(-4.25,-2.25) 48(-4.25,-2.75)
  silkscreen extent -3.52,-3.52 3.52,3.52, body extent -4.5,-4.5 4.5,4.5, height 1.6
ICC_TSSOP5_SOT353-1_2P05X1P25_P065 [mm] "MCD-01960"
  rect 0.45x0.9 smd mask+0.05: 1(-0.65,-0.875) 2(0,-0.875) 3(0.65,-0.875) 4(0.65,0.875) 5(-0.65,0.875)
  silkscreen extent -1.17,-1.25 1.12,0.67, body extent -1.23,-1.2 1.23,1.2, height 1.1
ICC_TSSOP20_6P50X4P40_P065 [mm]
  rect 0.4x1.6 smd mask+0.05: 1(-2.925,-2.8) 2(-2.275,-2.8) 3(-1.625,-2.8) 4(-0.975,-2.8) 5(-0.325,-2.8) 6(0.325,-2.8) 7(0.975,-2.8) 8(1.625,-2.8) 9(2.275,-2.8) 10(2.925,-2.8) 11(2.925,2.8) 12(2.275,2.8) 13(1.625,2.8) 14(0.975,2.8) 15(0.325,2.8) 16(-0.325,2.8) 17(-0.975,2.8) 18(-1.625,2.8) 19(-2.275,2.8) 20(-2.925,2.8)
  silkscreen extent -3.3,-2.25 3.3,2.25, body extent -3.3,-3.3 3.3,3.3, height 1.21
ICC_UFQFPN48-EPAD_7X7_H0P55_P050 [mm] "MCD-01704"
  rect 0.55x0.3 smd mask+0.05: 1(-3.375,2.75) 2(-3.375,2.25) 3(-3.375,1.75) 4(-3.375,1.25) 5(-3.375,0.75) 6(-3.375,0.25) 7(-3.375,-0.25) 8(-3.375,-0.75) 9(-3.375,-1.25) 10(-3.375,-1.75) 11(-3.375,-2.25) 12(-3.375,-2.75) 25(3.375,-2.75) 26(3.375,-2.25) 27(3.375,-1.75) 28(3.375,-1.25) 29(3.375,-0.75) 30(3.375,-0.25) 31(3.375,0.25) 32(3.375,0.75) 33(3.375,1.25) 34(3.375,1.75) 35(3.375,2.25) 36(3.375,2.75)
  rect 0.3x0.55 smd mask+0.05: 13(-2.75,-3.375) 14(-2.25,-3.375) 15(-1.75,-3.375) 16(-1.25,-3.375) 17(-0.75,-3.375) 18(-0.25,-3.375) 19(0.25,-3.375) 20(0.75,-3.375) 21(1.25,-3.375) 22(1.75,-3.375) 23(2.25,-3.375) 24(2.75,-3.375) 37(2.75,3.375) 38(2.25,3.375) 39(1.75,3.375) 40(1.25,3.375) 41(0.75,3.375) 42(0.25,3.375) 43(-0.25,3.375) 44(-0.75,3.375) 45(-1.25,3.375) 46(-1.75,3.375) 47(-2.25,3.375) 48(-2.75,3.375)
  rect 5.6x5.6 smd mask+0.05: 49(0,0)
  silkscreen extent -3.55,-3.55 3.55,3.55, body extent -3.5,-3.5 3.5,3.5, height 0.65
IND_0402_MURATA_LGQ15HS02_H0P5 [mm] "MCD-01461"
  rect 0.65x0.55 smd mask+0.05: 1(-0.475,0) 2(0.475,0)
  silkscreen extent -0.05,-0.28 0.05,0.28, body extent -0.53,-0.28 0.53,0.28, height 0.55
IND_0402_MURATA_LQW15AN_H0P5 [mm] "MCD-01606"
  rect 0.65x0.9 smd mask+0.05: 1(-0.475,0) 2(0.475,0)
  silkscreen extent -0.05,-0.35 0.05,0.35, body extent -0.55,-0.35 0.55,0.35, height 0.6
IND_0805_WURTH_74479777310A [mm] "MCD-01676"
  rect 0.7x1.45 smd mask+0.05: 1(-0.75,0) 2(0.75,0)
  silkscreen extent -0.28,-0.72 0.28,0.72, body extent -1.15,-0.72 1.15,0.72, height 1.45
L0603 [mm]
  rect 0.8x0.95 smd mask+0.05: 1(-0.8,0) 2(0.8,0)
  silkscreen extent -1.33,-0.6 1.33,0.6, body extent -0.87,-0.47 0.87,0.47, height 0.95
LED_0603_VISHAY_VLMB1300-GS08_BLUE_1A2K_H0P8 [mm]
  rect 0.8x0.8 smd mask+0.05: 1(-0.75,0) 2(0.75,0)
  silkscreen extent -0.85,-0.53 1.28,0.53, body extent -0.85,-0.45 0.85,0.45, height 0.8
LED_0603_VISHAY_VLMS1300-GS08_RED_1A2K_H0P8 [mm]
  rect 0.8x0.8 smd mask+0.05: 1(-0.75,0) 2(0.75,0)
  silkscreen extent -0.85,-0.53 1.28,0.53, body extent -0.85,-0.45 0.85,0.45, height 0.8
LED_0603_VISHAY_VLMTG1300-GS08_GREEN_1A2K_H0P8 [mm]
  rect 0.8x0.8 smd mask+0.05: 1(-0.75,0) 2(0.75,0)
  silkscreen extent -0.85,-0.53 1.28,0.53, body extent -0.85,-0.45 0.85,0.45, height 0.8
LED_BI-GR_HSMF-A201-A00J1 [mm] "MCD-00051"
  rect 1.1x1.5 smd mask+0.05: 1(-0.75,-1.5) 2(-0.75,1.5) 3(0.75,1.5) 4(0.75,-1.5)
  silkscreen extent -1.65,-1.85 1.5,1.7, body extent -1.5,-1.85 1.5,1.85, height 2.1
MOS_SOT23-5L [mm]
  rect 0.6x1.3 smd mask+0.05: 1(-0.95,-1.1) 2(0,-1.1) 3(0.95,-1.1) 4(0.95,1.1) 5(-0.95,1.1)
  silkscreen extent -1.6,-0.95 1.6,0.97, body extent -1.52,-1.25 1.52,1.25, height 1.45
NPN_SOT23 [mm]
  rect 1x1.4 smd mask+0.05: 1(-0.95,-1.1) 2(0.95,-1.1) 3(0,1.1)
  silkscreen extent -1.63,-0.82 1.63,0.82, body extent -1.56,-1.25 1.56,1.25, height 1.1
R0402 [mm]
  rect 0.51x0.7 smd mask+0.05: 1(-0.45,0) 2(0.45,0)
  silkscreen extent 0,-0.3 0,0.3, body extent -0.52,-0.3 0.52,0.3, height 0.4
REG_SOT23-5L [mm]
  rect 0.6x1.3 smd mask+0.05: 1(-0.95,-1.1) 2(0,-1.1) 3(0.95,-1.1) 4(0.95,1.1) 5(-0.95,1.1)
  silkscreen extent -1.6,-0.95 1.6,0.97, body extent -1.52,-1.25 1.52,1.25, height 1.1
REG_SOT223-TAB [mm]
  rect 1.5x1.65 smd mask+0.05: 1(-2.3,-3.175) 2(0,-3.175) 3(2.3,-3.175)
  rect 3.5x1.65 smd mask+0.05: 4(0,3.175)
  silkscreen extent -3.35,-2.15 3.35,2.12, body extent -3.35,-3.48 3.35,3.48, height 1.8
SHIELD_RF_ST-CUSTOM_17P2X17P2_H3 [mm] "MCD-02088"
  silkscreen extent -8.93,-8.93 8.93,8.93, body extent -8.6,-8.6 8.6,8.6, height 3
SOLDER-BRIDGE_R0402-0R [mil] "MCD-01619"
  round 10 smd paste-393.7 mask+4: 1(-17.72,0) 2(20.67,0)
  Top Layer region: -30.51,-13.78 -30.51,13.78 -8.37,13.78 -1.48,0 -8.37,-13.78
  Top Layer region: 1.48,13.78 8.37,0 1.48,-13.78 30.51,-13.78 30.51,13.78
  silkscreen extent -33,-17 33,17, body extent -20,-12 20,12, height 14
STICKER_BOARD_25X9 [mm] "Sticker to mention board CPN code"
  silkscreen extent -12.5,-4.5 12.5,4.5
STICKER_PRODUCT_25X9 [mm] "Sticker to mention board CPN code"
  silkscreen extent -12.5,-4.5 12.5,4.5
SWI_C&K_Y78B23110FP__ITT_KMR231GLFS [mm] "MCD-00715"
  rect 0.9x1 smd mask+0.05: 1(2.05,0.8) 2(2.05,-0.8) 3(-2.05,0.8) 4(-2.05,-0.8)
  rect 1.7x0.8 smd mask+0.05: 5(0,1.2)
  silkscreen extent -2.05,-1.43 2.05,1.43, body extent -2.3,-1.5 2.3,1.5, height 2.1
SWI_SPDT-RA_TE-CONNECTIVITY_MLL1200S_1P2T [mm] "MCD-02081"
  rect 1x0.8 smd mask+0.05: 0(-3.75,-1.15) 0(-3.75,1.15) 0(3.75,-1.15) 0(3.75,1.15)
  rect 0.7x1.1 smd mask+0.05: 1(-2.25,2.05) 2(0.75,2.05) 3(2.25,2.05)
  round 0.9 hole 0.9 unplated mask+0.05: NPTH1(-1.5,0) NPTH2(1.5,0)
  silkscreen extent -3.5,-2.9 3.5,1.4, body extent -3.85,-2.9 3.85,2.24, height 1.75

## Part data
B1 B2 B3 B4: library part MCD-01485, "Microminiature Tact Switch for SMT - KMR 2 Series - 1.9 mm height", Manufacturer=C&K, Manufacturer_Part_Number=KMR231GLFS
C3 C12 C14 C16 C17 C18 C19 C20 C24 C25 C26 C27 C28 C31 C32 C33 C41 C42 C43 C46 C47 C48 C49 C50: library part MCD-00006, "Capacitor, MLCC, 100nF, 16V, X7R, +/-10%, 0402, T=0.5mm", Alternate_Manufacturer=MURATA, Alternate_Manufacturer_Part_Number=GCM155R71C104KA55D, Manufacturer=YAGEO, Manufacturer_Part_Number=CC0402KRX7R7BB104, Package=C0402
C6 C7: library part MCD-00015, "Capacitor, MLCC, 10pF, 50V, NPO, +/-5%, 0402, T=0,5mm", Manufacturer=YAGEO, Manufacturer_Part_Number=CC0402JRNPO9BN100, Package=C0402
C8: library part MCD-01099, "Capacitor, MLCC, 100nF, 50V, X7R, +/-10%, 0603, T=0.8mm", Manufacturer=YAGEO, Manufacturer_Part_Number=CC0603KRX7R9BB104, Package=C0603
C9 C10: library part MCD-00014, "Capacitor, MLCC, 10uF, 25V, X5R, +/-10%, 0805, T=0,85mm", Manufacturer=YAGEO, Manufacturer_Part_Number=CC0805KRX5R8BB106, Package=C0805
C11: library part MCD-00007, "Capacitor, Tantalum, 4.7uF, 16V, 4ohms, +/-10%, pkg Type_A (3216 metric), T=1.6mm", Manufacturer=AVX, Manufacturer_Part_Number=TAJA475K016R, Package=Type_A
C13 C15 C21 C22: library part MCD-00010, "Capacitor, MLCC, 1uF, 16V, X5R, +/-10%, 0603, T=0,8mm", Manufacturer=YAGEO, Manufacturer_Part_Number=CC0603KRX5R7BB105, Package=C0603
C23 C29: library part MCD-01356, "Capacitor, MLCC, 4.7uF, 6V3, X5R, +/-20%, 0402, T=0,5mm", Alternate_Manufacturer=MURATA, Alternate_Manufacturer_Part_Number=GRM155R60J475ME87, Manufacturer_Part_Number=GRM155R60J475ME47, Package=C0402
C34 C51: library part MCD-00205, "Capacitor,MLCC,100pF,50V,NPO,+/-5%,0402,T=0,5mm", Manufacturer=YAGEO, Manufacturer_Part_Number=CC0402JRNPO9BN101, Package=C0402
C36 C37 C39 C40: library part MCD-02065, "Capacitor, High Q type for high frequency and high power, SMD, 1.2pF, 50V, 0,05pf, 0402", Alternate_Manufacturer=N/A, Manufacturer=MURATA, Manufacturer_Part_Number=GJM1555C1H1R2WB01D, Package=C0402
C44 C45: library part MCD-00016, "Capacitor, MLCC, 20pF, 50V, NPO, +/- 5%, 0402, T=0,5mm", Manufacturer=YAGEO, Manufacturer_Part_Number=CC0402JRNPO9BN200, Package=C0402
CN2: library part MCD-02071, "Battery Coin Cell holder, CR2032_20mm, Height 5.4mm", Alternate_Manufacturer=1060TR, Alternate_Manufacturer_Part_Number=KEYSTONE, Manufacturer=RENATA, Manufacturer_Part_Number=SMTU2032-LF, Package=N/A
CN3: library part MCD-02060, "Header, 5x1, 2,54mm, VR, TH, Height 5.84mm/2.54mm", Alternate_Manufacturer=N/A, Manufacturer=SAMTEC, Manufacturer_Part_Number=TSW-105-07-G-S
CN4 CN14: library part MCD-00032, "Header, 2x1, 2,54mm, VR, TH, Height 5.84mm/2.54mm", Alternate_Manufacturer=JIUBABA, Alternate_Manufacturer_Part_Number=313102S111116, Manufacturer=SAMTEC, Manufacturer_Part_Number=TSW-102-07-G-S
CN5: library part MCD-02080, "Socket 10x1, 2.54mm, VR, TH, height 8.51/2.64mm", Alternate_Manufacturer=JIUBABA, Alternate_Manufacturer_Part_Number=218110S16198, Manufacturer=SAMTEC, Manufacturer_Part_Number=SSW-110-01-G-S, Package=N/A
CN6 CN9: library part MCD-01743, "Socket 8x1, 2.54mm, VR, TH, height 8.51/2.64mm", Alternate_Manufacturer=Jiubaba, Alternate_Manufacturer_Part_Number="988.08.18.2.00050 (218108S16198)", Manufacturer=SAMTEC, Manufacturer_Part_Number=SSW-108-01-G-S
CN7 CN10: library part MCD-00213, "Header, 19x2, 2,54mm, VR, TH, Height 5.84mm/10.16mm", Manufacturer=SAMTEC, Manufacturer_Part_Number=TSW-119-09-G-D
CN8: library part MCD-02079, "Socket 6x1, 2.54mm, VR, TH, height 8.51/2.64mm", Alternate_Manufacturer=JIUBABA, Alternate_Manufacturer_Part_Number=218106S16198, Manufacturer=SAMTEC, Manufacturer_Part_Number=SSW-106-01-G-S, Package=N/A
CN11 CN12 JP2 JP3 JP4 JP6: library part MCD-00683, "Header, 2x1, 2,54mm, VR, TH, Height 5.84mm/2.54mm - Shunt Fitted by default", Alternate_Manufacturer=LIANYI, Alternate_Manufacturer_Part_Number=313102S111116, Manufacturer=SAMTEC, Manufacturer_Part_Number=TSW-102-07-G-S
CN13: library part MCD-00212, "Header, 6x1, 2,54mm, VR, TH, Height 5.84mm/2.54mm", Manufacturer=SAMTEC, Manufacturer_Part_Number=TSW-106-07-G-S
CN15: library part MCD-00028, "USB-MICRO-B, 0.65mm, RA, SMT, Bottom Mount,", Manufacturer=MOLEX, Manufacturer_Part_Number=1050170001
D1: library part MCD-01677, "Small signal Schottky diodes", Manufacturer=STMICROELECTRONICS, Manufacturer_HQ_COO=EU, Manufacturer_Part_Number=BAT54KFILM, Package=SOD-523
D2: library part MCD-00034, Manufacturer=STMICROELECTRONICS, Manufacturer_HQ_COO=EU
HW16: library part MCD-00235, "Sticker Board 25x9 mm", Alternate_Manufacturer=N/A
HW18: library part MCD-00547, "Sticker product 25x9 mm", Alternate_Manufacturer=N/A
HW20: library part MCD-02088, "RF shield (17,2x17,2x3mm), Brass with Sn finishing, Sheet tickness : 0,2mm", Alternate_Manufacturer=N/A, Manufacturer_Part_Number="RF shield (17,2x17,2x3mm)"
J2: library part MCD-02072, "RF SMA connector PCB edge", Alternate_Manufacturer=N/A, Manufacturer=JOHNSON, Manufacturer_Part_Number=142-0701-851
JP1: library part MCD-00633, "Header, 4x2, 2,54mm, VR, TH, Height 5.84mm/2.54mm", Manufacturer=SAMTEC, Manufacturer_Part_Number=TSW-104-07-G-D
JP5: library part MCD-02061, "Header, 8x2, 2,54mm, VR, TH, Height 5.84mm/2.54mm", Alternate_Manufacturer=N/A, Manufacturer=SAMTEC, Manufacturer_Part_Number=TSW-108-07-G-D
L1: library part MCD-01461, "Inductor, LQG15H, 3.6nH, +-0.3nH 0402", Manufacturer=MURATA, Manufacturer_Part_Number=LQG15HS3N6S02, Package=0402
L4: library part MCD-01676, "PMI Series 10 μH ±20% Multilayer SMD Inductor, 0805 25MHz 650mA dc 500mΩ Rdc", Alternate_Manufacturer=N/A, Manufacturer="WURTH ELEKTRONIK", Manufacturer_Part_Number=74479777310A, Package="2x1.25x1.2 mm"
L5: library part MCD-02063, "inductor, 10nH +-2%, 100mA max,1.3 ohm DC max, Q min = 13,0402", Alternate_Manufacturer="WURTH ELECTRONIK", Alternate_Manufacturer_Part_Number=744901110, Manufacturer=MURATA, Manufacturer_Part_Number=LQP15MN10NG02, Package=L0402
L6: library part MCD-00047, "SMD Chip ferrite bead, 600R@100MHz +/-25%, 350mA, 500mohm DC, 0603, T=0.8mm", Manufacturer=TAI-TECH, Manufacturer_Part_Number=FCM1608KF-601T03
LD1: library part MCD-00584, "LED Blue, 0603 SMD, 3.3 V Forward Voltage", Manufacturer=VISHAY, Manufacturer_Part_Number=VLMB1300-GS08, Package="LED 0603"
LD2 LD5: library part MCD-00589, "LED Green, 0603 SMD, Fw Voltage = 2.8V - 3.6V", Alternate_Manufacturer="OSRAM OPTO SEMICONDUCTORS", Alternate_Manufacturer_Part_Number="LG Q396-PS-35", Manufacturer=VISHAY, Manufacturer_Part_Number=VLMTG1300-GS08, Package="LED 0603"
LD3 LD4: library part MCD-00587, "LED Red, 0603 SMD, 2V Forward Voltage", Alternate_Manufacturer="OSRAM OPTO SEMICONDUCTORS", Alternate_Manufacturer_Part_Number="LS Q976-NR-1", Manufacturer=VISHAY, Manufacturer_Part_Number=VLMS1300-GS08, Package="LED 0603"
LD6: library part MCD-00051, "LED Bicolor", Alternate_Manufacturer=EVERLUCK, Alternate_Manufacturer_Part_Number=LE-RGW35280, Manufacturer="AVAGO TECHNOLOGIES", Manufacturer_Part_Number=HSMF-A201-A00J1
Q1: library part MCD-00073, "NPN Bipolar Transistor", Alternate_Manufacturer="ON SEMICONDUCTOR", Alternate_Manufacturer_Part_Number="MMBT2222LT1G / MMBT2222ALT1G / MMBT2222ALT3G", Manufacturer_Part_Number=BSR14, Package=SOT23
R1 R5 R13: library part MCD-00052, "Resistor,0R,0402,5%,1/16W", Manufacturer=YAGEO, Manufacturer_Part_Number=RC0402JR-070RL, Package=R0402
R2 R3 R4: library part MCD-00507, "Resistor,680R,0402,1%,1/16W", Manufacturer=YAGEO, Manufacturer_Part_Number=RC0402FR-07680RL, Package=R0402
R6 R11 R16 R18 R22 R30: library part MCD-00053, "Resistor,10K,0402,1%,1/16W", Manufacturer=YAGEO, Manufacturer_Part_Number=RC0402FR-0710KL, Package=R0402
R7 R8 R9 R12 R33: library part MCD-00061, "Resistor,1K,0402,1%,1/16W", Manufacturer=YAGEO, Manufacturer_Part_Number=RC0402FR-071KL, Package=R0402
R10: library part MCD-00441, "Resistor,270R,0402,1%,1/16W", Manufacturer=YAGEO, Manufacturer_Part_Number=RC0402FR-07270RL, Package=R0402
R14: library part MCD-00055, "Resistor,2K7,0402,1%,1/16W", Manufacturer=YAGEO, Manufacturer_Part_Number=RC0402FR-072K7L, Package=R0402
R15 R26 R28: library part MCD-00065, "Resistor,4K7,0402,1%,1/16W", Alternate_Manufacturer=YAGEO, Alternate_Manufacturer_Part_Number=RT0402FRE074K7L, Manufacturer_Part_Number=RC0402FR-074K7L, Package=R0402
R17 R25 R27 R29: library part MCD-00067, "Resistor,100R,0402,1%,1/16W", Manufacturer=YAGEO, Manufacturer_Part_Number=RC0402FR-07100RL, Package=R0402
R19 R23 R24 R32: library part MCD-00059, "Resistor,100K,0402,1%,1/16W", Alternate_Manufacturer=YAGEO, Alternate_Manufacturer_Part_Number=RT0402FRE07100KL, Manufacturer_Part_Number=RC0402FR-07100KL, Package=R0402
R20: library part MCD-00069, "Resistor,36K,0402,1%,1/16W", Manufacturer=YAGEO, Manufacturer_Part_Number=RC0402FR-0736KL, Package=R0402
R21: library part MCD-00068, "Resistor,1K5,0402,1%,1/16W", Manufacturer=YAGEO, Manufacturer_Part_Number=RC0402FR-071K5L, Package=R0402
R31: library part MCD-00358, "Resistor,10R,0402,1%,1/16W", Manufacturer=YAGEO, Manufacturer_Part_Number=RC0402FR-0710RL, Package=R0402
SB5 SB6 SB10 SB11 SB12 SB13 SB14 SB15 SB16 SB17 SB19 SB20 SB21 SB22 SB23 SB24 SB25 SB26 SB27 SB28 SB29 SB30 SB31 SB32: library part MCD-01618, "Solder Bridge 0402 ON", Manufacturer=YAGEO, Manufacturer_Part_Number=RC0402JR-070RL, Package=SB0402
SC1 SC2 SC3 SC4: library part MCD-01587, "shield clip Harwin S0951-46R to fix RF shielded cavity", Alternate_Manufacturer=N/A, Manufacturer=HARWIN, Manufacturer_Part_Number=S0951-46R
SW5: library part MCD-02081, "SPDT RA SMT SLIDE SWITCH", Alternate_Manufacturer=N/A, Manufacturer="TE CONNECTIVITY", Manufacturer_Part_Number=MLL1200S
U1: library part MCD-02058, "Multiprotocol wireless 32-bit MCU ARM®-based Cortex®-M4 with FPU, Bluetooth® Low-Energy and 802.15.4 radio solution", Alternate_Manufacturer=N/A, Manufacturer=STMICROELECTRONICS, Manufacturer_HQ_COO=EU, Manufacturer_Part_Number=STM32WB15CCU6, Package=UFQFPN48
U2: library part MCD-00088, "IC REG LDO 5V 0.8A SOT223", Manufacturer=STMICROELECTRONICS, Manufacturer_HQ_COO=EU, Package=SOT-223
U3: library part MCD-00215, "Low quiescent current and low noise voltage regulators", Manufacturer=STMICROELECTRONICS, Manufacturer_HQ_COO=EU, Package="DFN6 3x3mm"
U4: library part MCD-01785, "5V Power Switch, 0.85A, RDSon 130mOhm max, with active low enable pin", Manufacturer="TEXAS INSTRUMENTS", Manufacturer_Part_Number=TPS2041CDBVT, Package=SOT23_5p
U5: library part MCD-00086, "Ultra low drop-low noise BiCMOS voltage, regulators low ESR capacitors compatible", Manufacturer=STMICROELECTRONICS, Manufacturer_HQ_COO=EU
U7: library part MCD-00289, "8bits_bidirectionnal level shifter, Delay 312ns/1V8", Manufacturer="TEXAS INSTRUMENTS"
U8: library part MCD-00085, "Medium-density performance line ARM-based 32-bit MCU with 128KB Flash", Manufacturer=STMICROELECTRONICS, Manufacturer_HQ_COO=EU
U9: library part MCD-00649, "Common mode filter with ESD protection for USB 2.0 interface", Manufacturer=STMICROELECTRONICS, Manufacturer_HQ_COO=EU
U10: library part MCD-01960, "Buffer/Driver 1-CH Non-Inverting Open Drain CMOS Automotive 5-Pin TSSOP T/R", Manufacturer=NEXPERIA, Package=TSSOP5
U12: library part MCD-00251, "High power transient voltage suppressor, 7V breakdown", Manufacturer=STMICROELECTRONICS, Manufacturer_HQ_COO=EU, Manufacturer_Part_Number=ESDA7P60-1U1M
U13: library part MCD-02059, "2.4 GHz low pass filter matched to STM32WBx5Cx/Rx", Alternate_Manufacturer=N/A, Manufacturer=STMICROELECTRONICS, Manufacturer_HQ_COO=EU, Package="Bumpless CSP"
X1: library part MCD-01446, "Crystal 32MHz, 8pF, +-10ppm, 60ohms max, SMD", Manufacturer=NDK, Manufacturer_Part_Number="NX2016SA 32MHz EXS00A-CS06654", Package=NX2016SA
X2: library part MCD-01445, "Crystal 32.768kHz, 7pF, +-20ppm, 80Kohms max, SMD", Manufacturer=NDK, Manufacturer_Part_Number="NX2012SA 32.768kHz EXS00A-MU00389", Package=NX2012SA
X3: library part MCD-00092, "Crystal 8MHz, 8pF, +-20ppm, 500ohms max,  SMD", Manufacturer=NDK, Manufacturer_Part_Number="NX3225GD 8MHz EXS00A-CG04874"

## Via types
v1: diameter 0.4, hole 0.2, Top Layer to Bottom Layer, tented both sides, 1003 vias
v2: diameter 0.4/0.4/0.3/0.4 (per signal layer), hole 0.2, Top Layer to Bottom Layer, tented both sides, 89 vias

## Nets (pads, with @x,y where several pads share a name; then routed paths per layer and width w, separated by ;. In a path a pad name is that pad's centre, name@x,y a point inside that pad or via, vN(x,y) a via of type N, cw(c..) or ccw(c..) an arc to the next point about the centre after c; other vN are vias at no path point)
3V3: C13.2 C16.2 CN6.2 CN6.4 CN7.12 CN7.16 SB14.1 SB21.1 U3.4 | length 89
  Top Layer w0.508: SB21.1@20.839,37.95 20.839,36.528 22.623,34.744 23.007,34.744 23.5,34.251 26.521,34.251 v1(28.021,32.752)
  Top Layer w1: CN7.12@6.04,38.52 CN6.2@11.12,38.52 ; CN6.4@11.12,33.46 12.93,31.65 12.93,29.795 14.251,28.473 22.394,28.473 23.067,27.8 v1(29.35,27.8) 34.69,27.8 35.554,28.664 38.886,28.664 39.55,28 45.445,28 47.245,29.8 53.317,29.8 56.08,32.564 56.08,38.343
  Bottom Layer w0.5: v1(28.021,32.752) 28.021,32.145 29.35,30.816 v1(29.35,27.8)
  Bottom Layer w1: CN7.16@6.04,33.44 CN6.4@11.12,33.44 12.81,35.13 12.81,36.83 CN6.2@11.12,38.52
3V3_STLINK: C22.2 C27.2 C41.1 C43.1 C47.2 C48.2 C49.2 C50.2 LD6.4 Q1.3 R24.2 R30.1 R31.2 R32.2 SB29.1 U5.5 U7.19 U8.1 U8.9 U8.24 U8.36 U8.48 U10.5 | length 87.6
  Top Layer w0.3: v1(36.17,17.38) 36.22,17.38 36.53,17.07 C43.1@37,17.07 37.18,16.89 U10.5@37.925,16.89 38.457,16.89 38.959,16.388 40.438,16.388 R32.2@40.7,16.65 ; U7.19@37.152,25.275 C41.1@38.763,25.275 38.763,24.464 39.662,23.564 v1(39.662,22.56) ; v1(39.97,12.95) C48.2@40.77,12.95 ; C48.2@40.91,12.95 41.3,12.95 41.894,13.544 U8.24@42.345,13.544 ; U8.9@45.345,20.544 45.345,21.426 44.87,21.901 C50.2@44.87,22.55 v1(45.6,22.55) ; R24.2@46.5,23.45 v1(46.5,24.1) ; U8.36@49.345,12.044 49.345,11.243 49.55,11.038 C47.2@49.55,10.591 v1(49.55,9.805) ; U8.1@49.345,20.544 49.345,21.014 49.531,21.2 v1(50.41,21.2) ; U8.48@50.845,19.044 51.258,19.044 51.764,19.55 C49.2@52.3,19.55 v1@52.3,20.161 ; Q1.3@54.1,11.6 55.101,11.6 55.82,12.319 R31.2@56.28,12.319 56.28,11.78 v1(55.9,11.4)
  Top Layer w0.5: v1(38.4,14.6) R30.1@39.212,14.6 ; LD6.4@47.27,4 v1(47.27,5.3) ; SB29.1@53.323,17.234 v1(53.323,18.015)
  VCC w0.5: v1(39.97,12.95) 43.22,12.95 45.693,10.477 47.27,10.477 47.27,10.447 ; v1(47.27,5.3) 47.27,10.447 ; v1(55.9,11.4) 54.1,11.4 52.505,9.805 v1(49.55,9.805) 49.55,9.857 48.93,10.477 47.3,10.477 47.27,10.447
  Bottom Layer w0.5: v1(36.17,17.38) 38.459,17.38 39.172,16.667 39.745,16.667 ; 37.353,13.45 38.55,13.45 39.449,14.349 39.449,14.488 39.745,14.784 39.745,16.667 ; v1(46.5,24.1) 46.5,23.45 v1(45.6,22.55) 44.97,23.18 40.282,23.18 v1(39.662,22.56) 39.662,19.273 39.745,19.19 39.745,16.667 ; v1(50.41,21.2) 51.3,21.2 v1(52.3,20.2) 52.3,18.471 52.756,18.015 v1(53.323,18.015) 53.323,14.535 55.9,11.958 v1(55.9,11.4)
5V: C14.2 C15.2 CN6.5 CN7.18 D2.1 JP1.2 JP1.4 JP1.6 JP1.8 R10.2 SB17.2 U3.1 U3.6 | length 100
  Top Layer w0.5: v1(52.898,21.77) D2.1@53.7,21.77
  Top Layer w1: JP1.2@43.303,47.27 JP1.4@45.843,47.27 JP1.6@48.383,47.27 JP1.8@50.923,47.27 52.33,47.27 52.7,46.9
  VCC w0.8: CN6.5@11.12,30.9 11.22,30.9 15.42,35.1 22.432,35.1 23.212,34.32 27.91,34.32 29.49,32.74 32.3,32.74 33.21,31.83 34.95,31.83 37.173,29.607 37.173,26.817 38.39,25.6 39.28,25.6 45.84,25.6 ; JP1.8@50.923,47.27 52.375,45.818 52.375,43.335 45.84,36.8 45.84,25.6 ; v1(52.898,21.77) 51.64,21.77 47.81,25.6 45.84,25.6
  Bottom Layer w0.8: 36.94,42.364 37.737,43.16 40.047,43.16 41.3,44.413 41.3,45.322 43.248,47.27 JP1.2@43.303,47.27
  Bottom Layer w1: CN7.18@6.04,30.9 CN6.5@11.12,30.9
5V_EXT: CN7.6 JP1.1 | length 59
  VCC w0.5: CN7.6@6.04,46.14 7.791,47.891 7.791,56.031 8.36,56.6 13.035,56.6 14.612,55.023 14.612,50.501 17.511,47.602 19.9,47.602 21.02,46.482 24.595,46.482 25.019,46.906 25.019,49.52 25.55,50.051 31.829,50.051 32.38,49.5 39.604,49.5 40.832,48.272 40.832,47.201 JP1.1@43.303,44.73
5V_INT: C10.1 JP1.3 R33.2 U2.2 U2.4 | length 34.9
  Top Layer w0.5: v1@35.027,32.7 35.547,32.7 35.956,33.109 35.956,33.456 37.61,35.109 U2.2@38.739,35.109
  Top Layer w1: JP1.3@45.843,44.73 45.843,41.274 45.976,41.141
  VCC w0.5: v1(14.175,38.608) 14.175,37.975 16.15,36 22.739,36 23.559,35.18 29.674,35.18 31.089,33.765 32.592,33.765 33.649,32.707 v1(35.006,32.707)
  Bottom Layer w0.5: v1(14.175,38.608) 14.175,39.907 14.8,40.532 R33.2@14.8,41.06
5V_USB_MCU: CN10.8 JP1.5 | length 21.2
  Bottom Layer w0.4: JP1.5@48.383,44.73 49.653,46 55.858,46 58,43.858 62.142,43.858 63.688,42.312 65.712,42.312 CN10.8@67,43.6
